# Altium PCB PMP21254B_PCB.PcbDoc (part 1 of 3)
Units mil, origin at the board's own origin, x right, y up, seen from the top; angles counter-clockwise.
Board outline 5000 x 7000 mil, 8 copper layers (Top Layer, Signal Layer 1, Signal Layer 2, Signal Layer 3, Signal Layer 4, Signal Layer 5, Signal Layer 6, Bottom Layer), stack 63 mil thick; 205 components, 78 nets, 623 pads, 1087 vias.
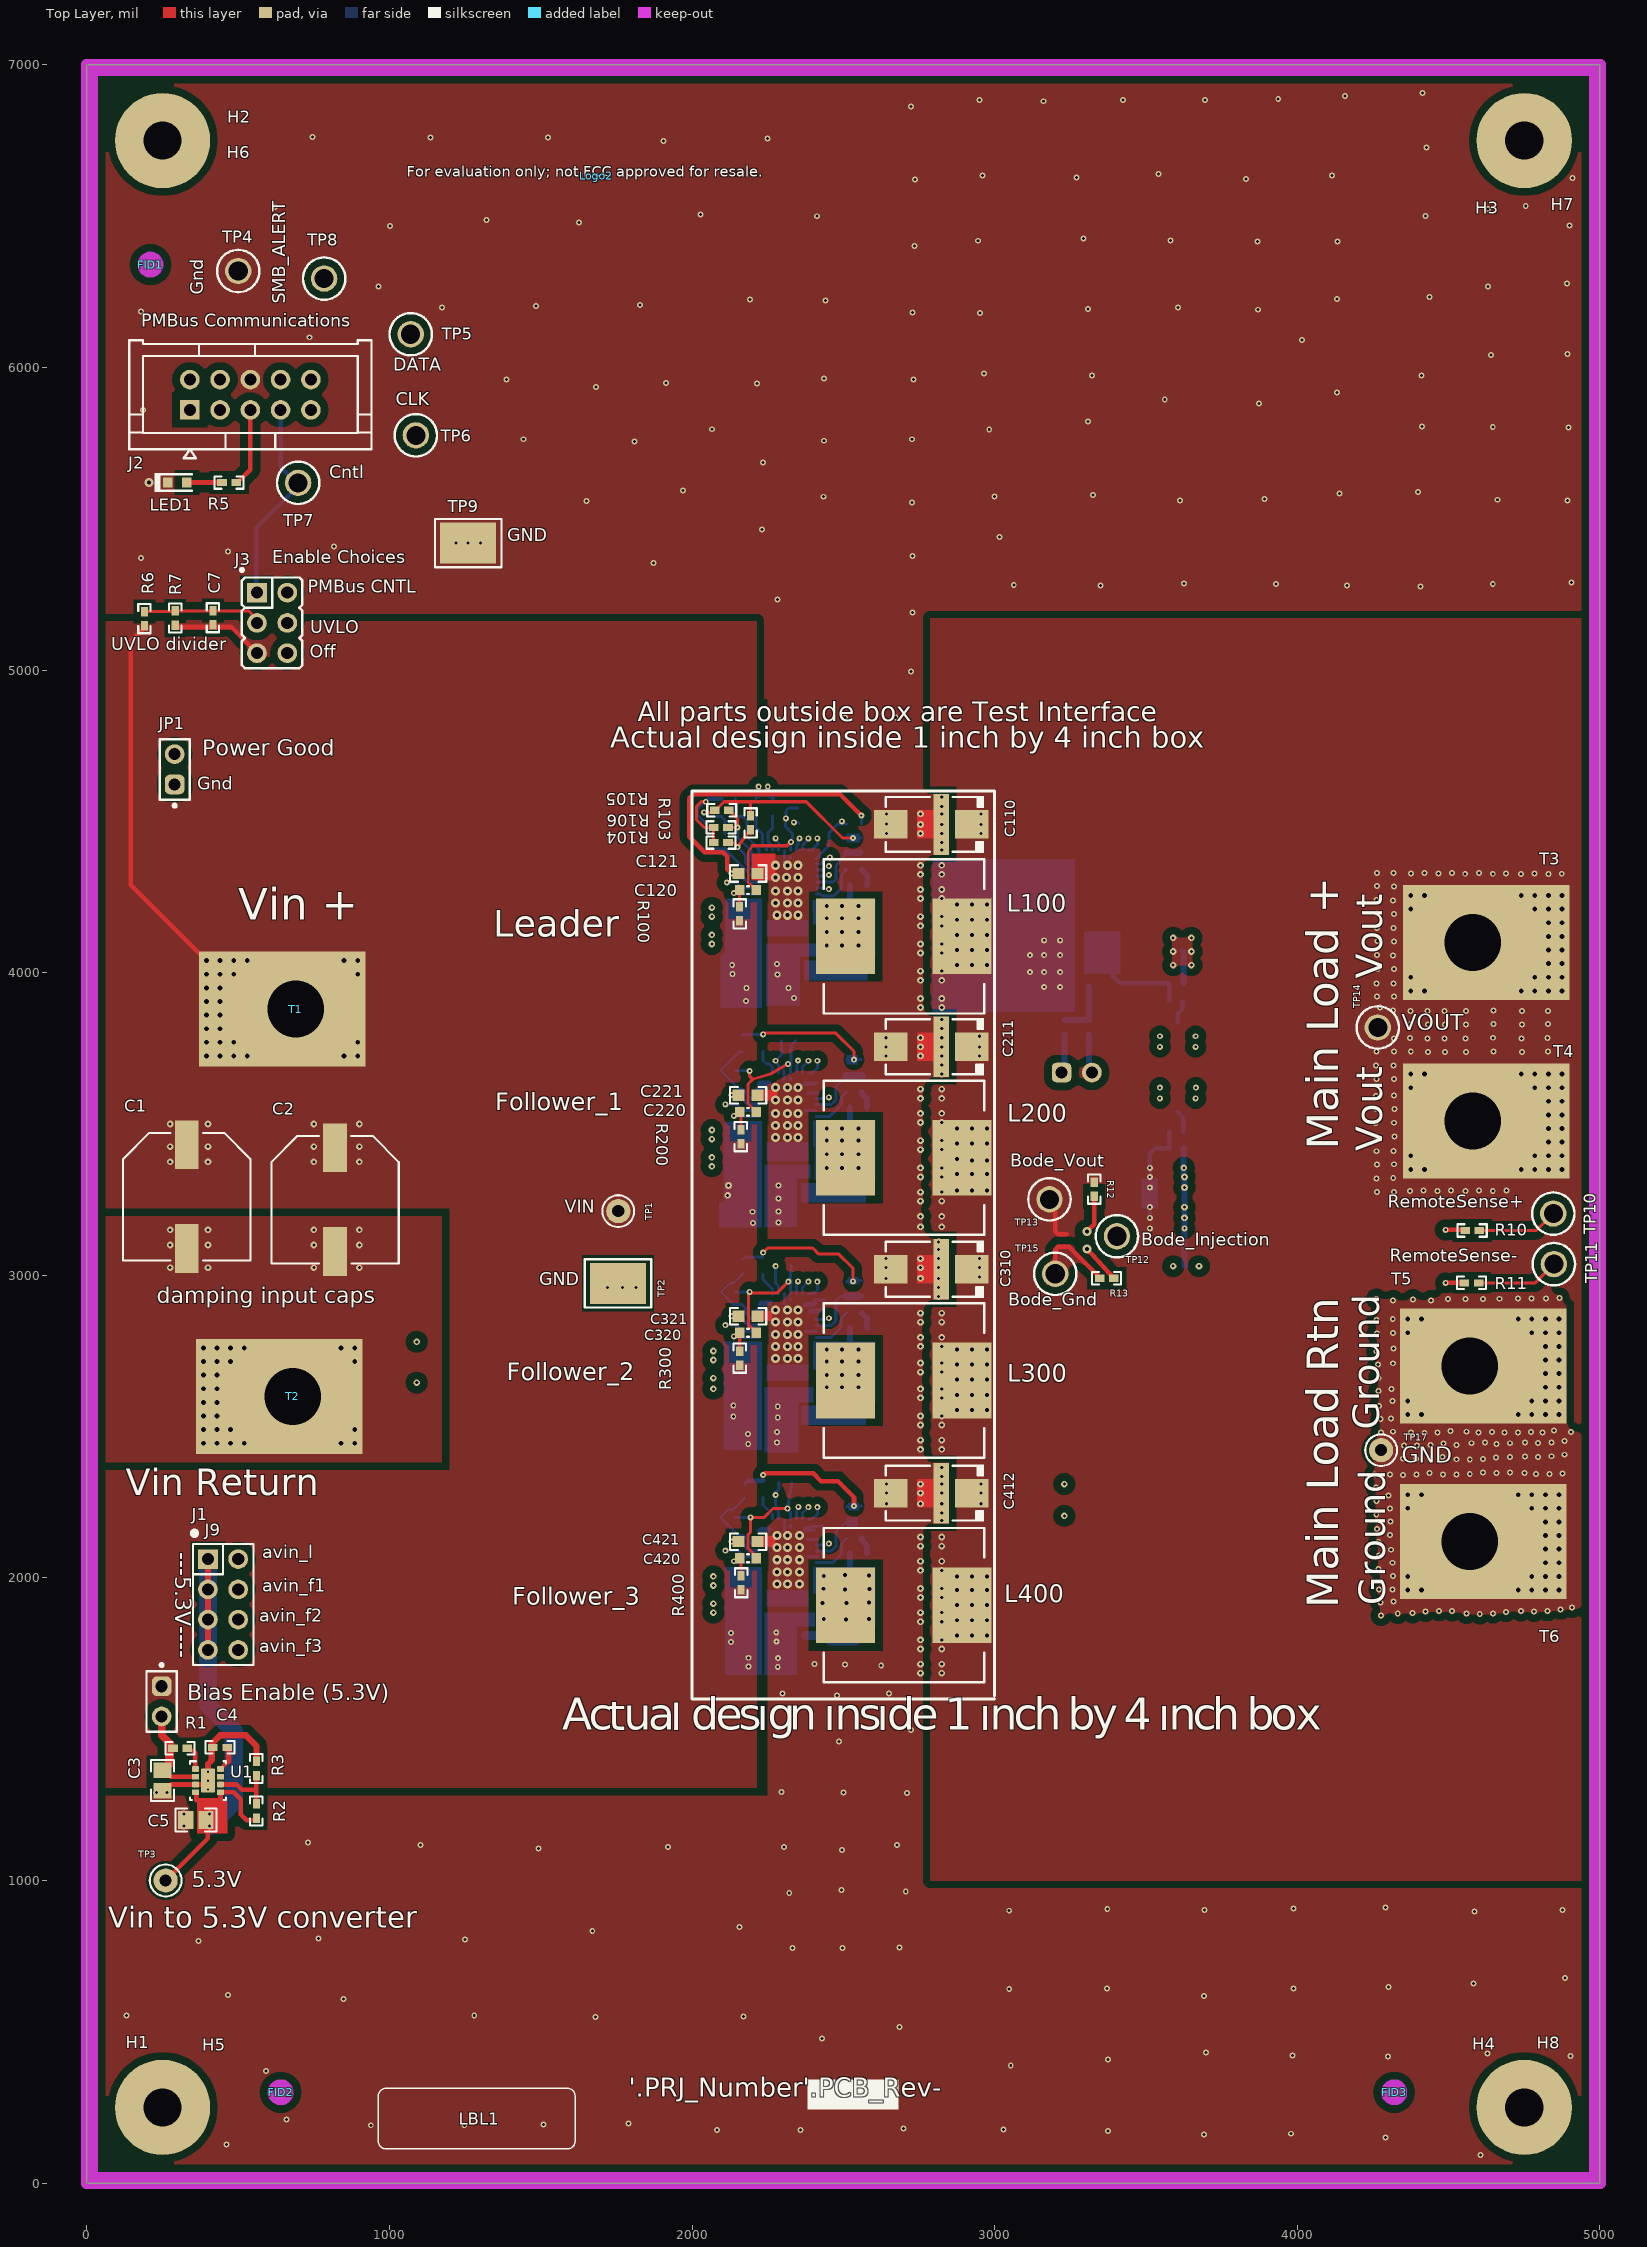
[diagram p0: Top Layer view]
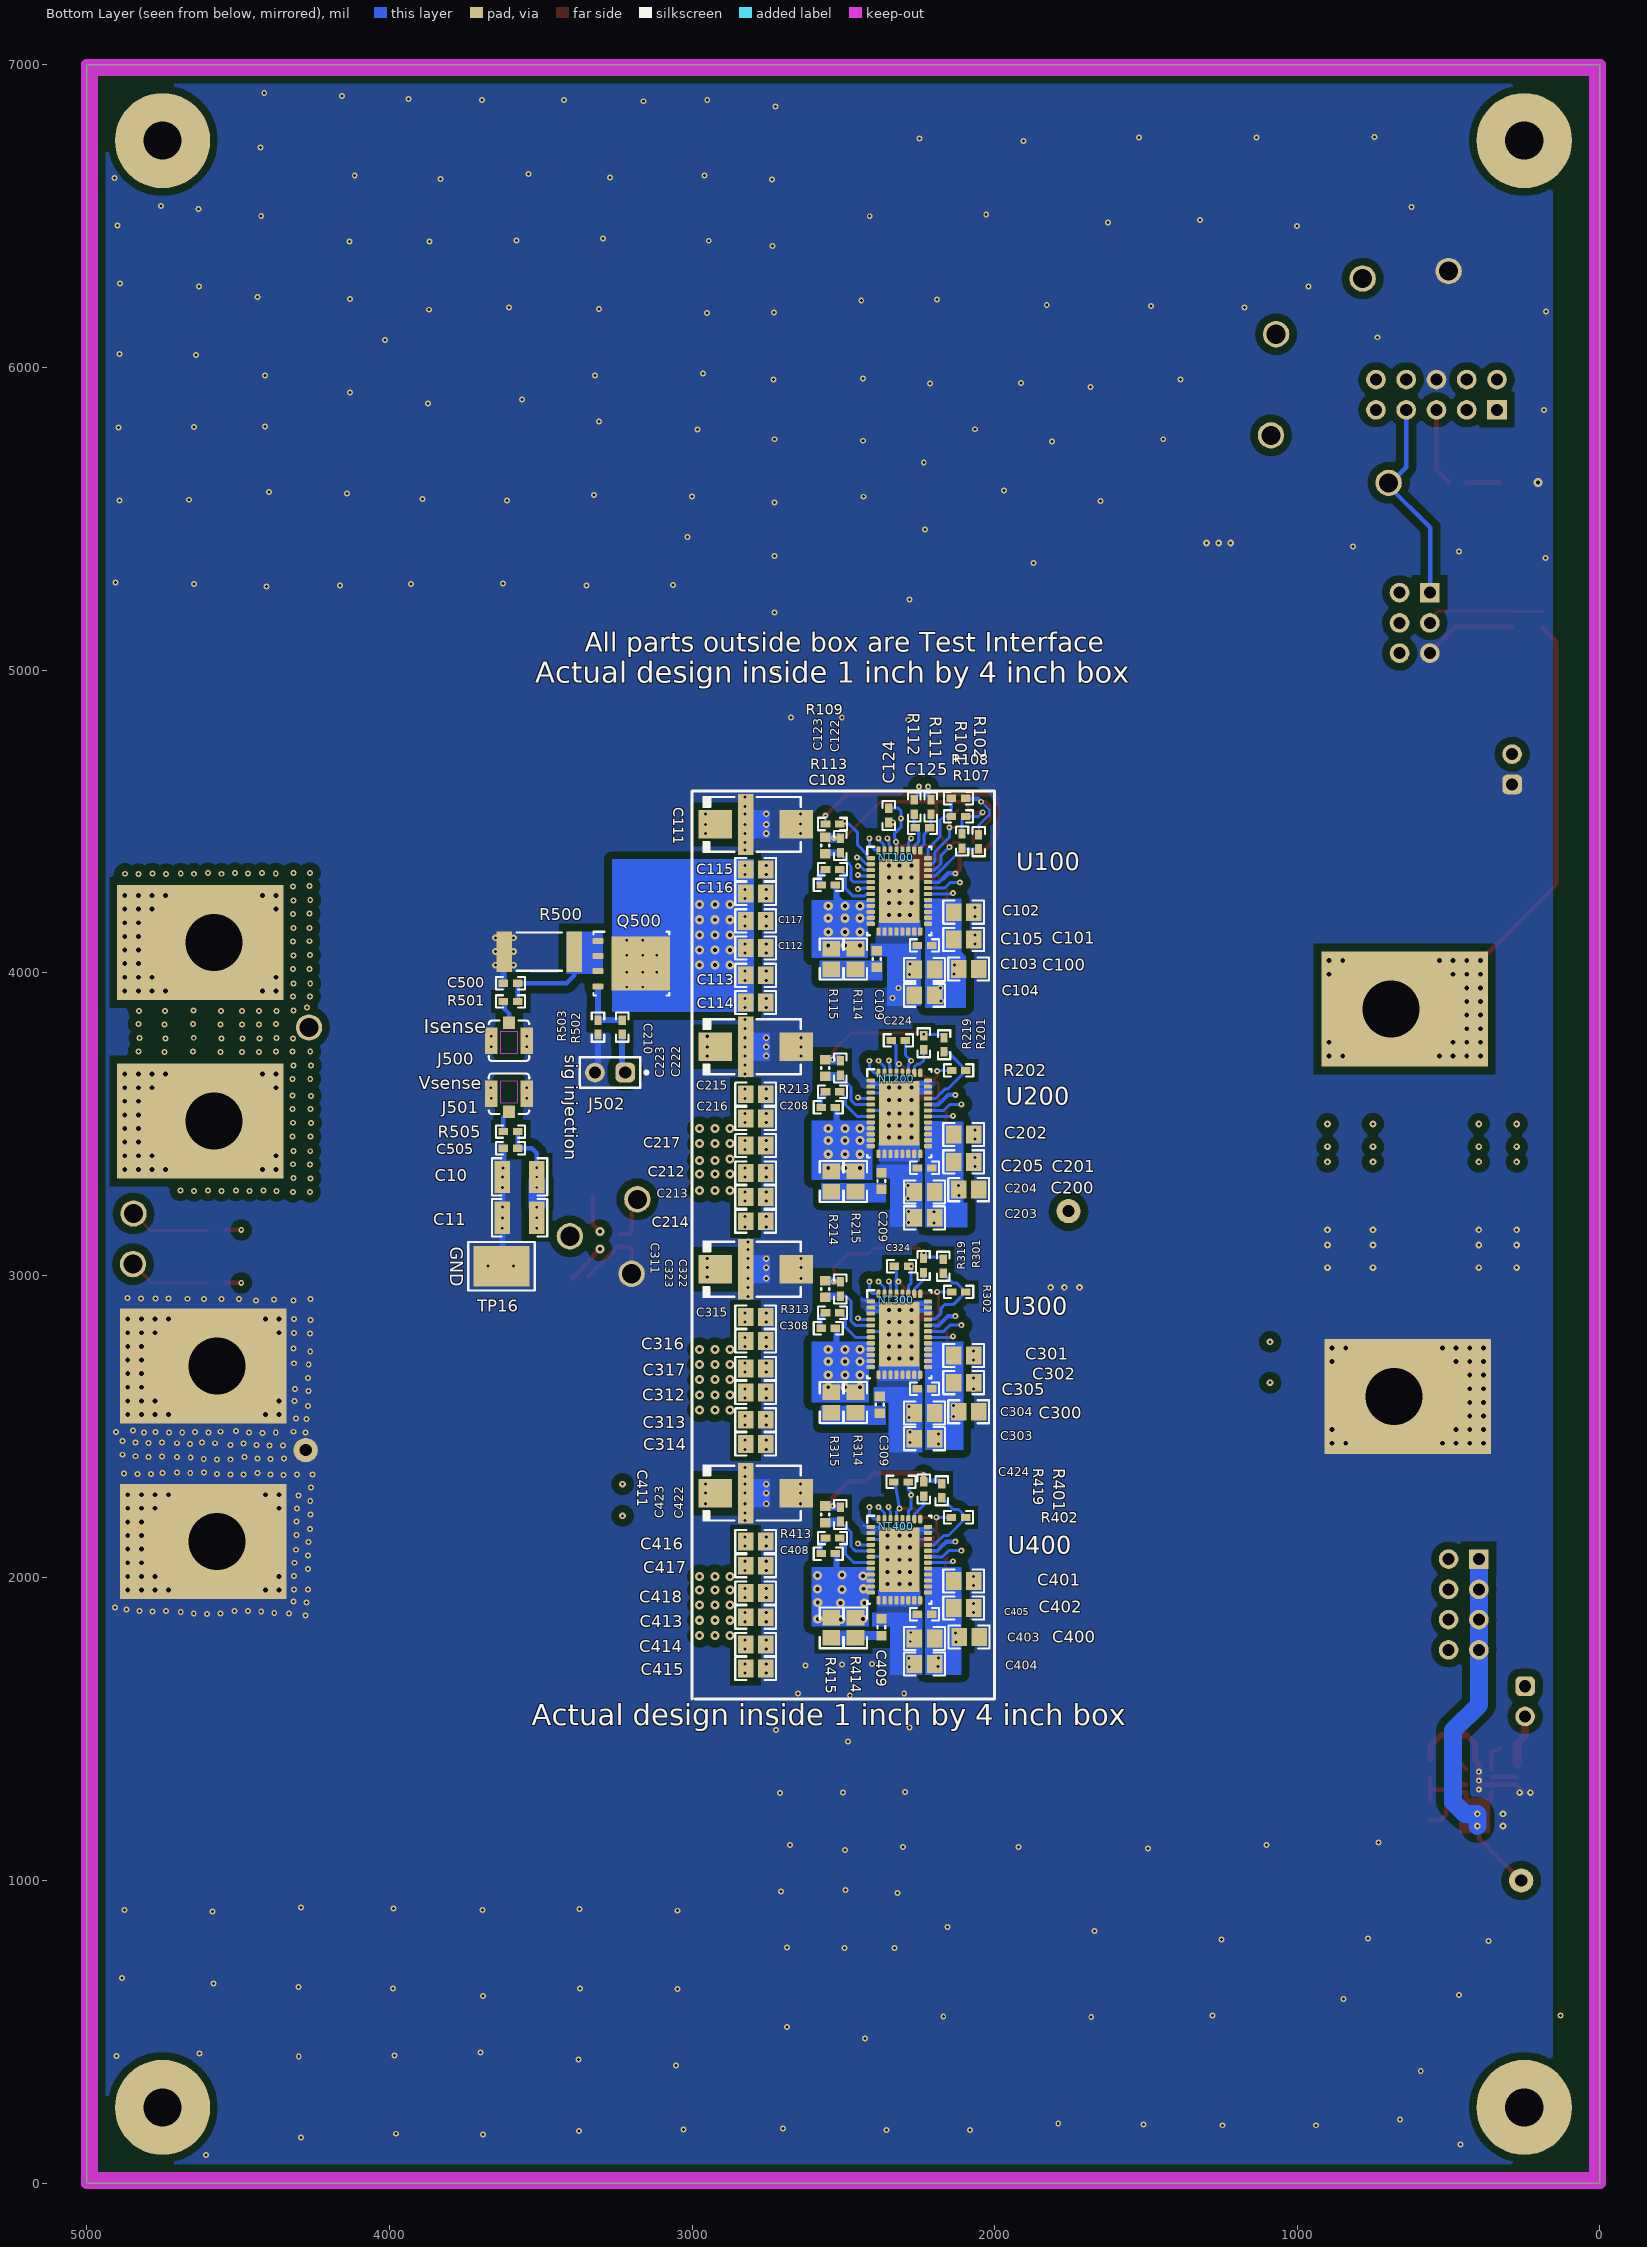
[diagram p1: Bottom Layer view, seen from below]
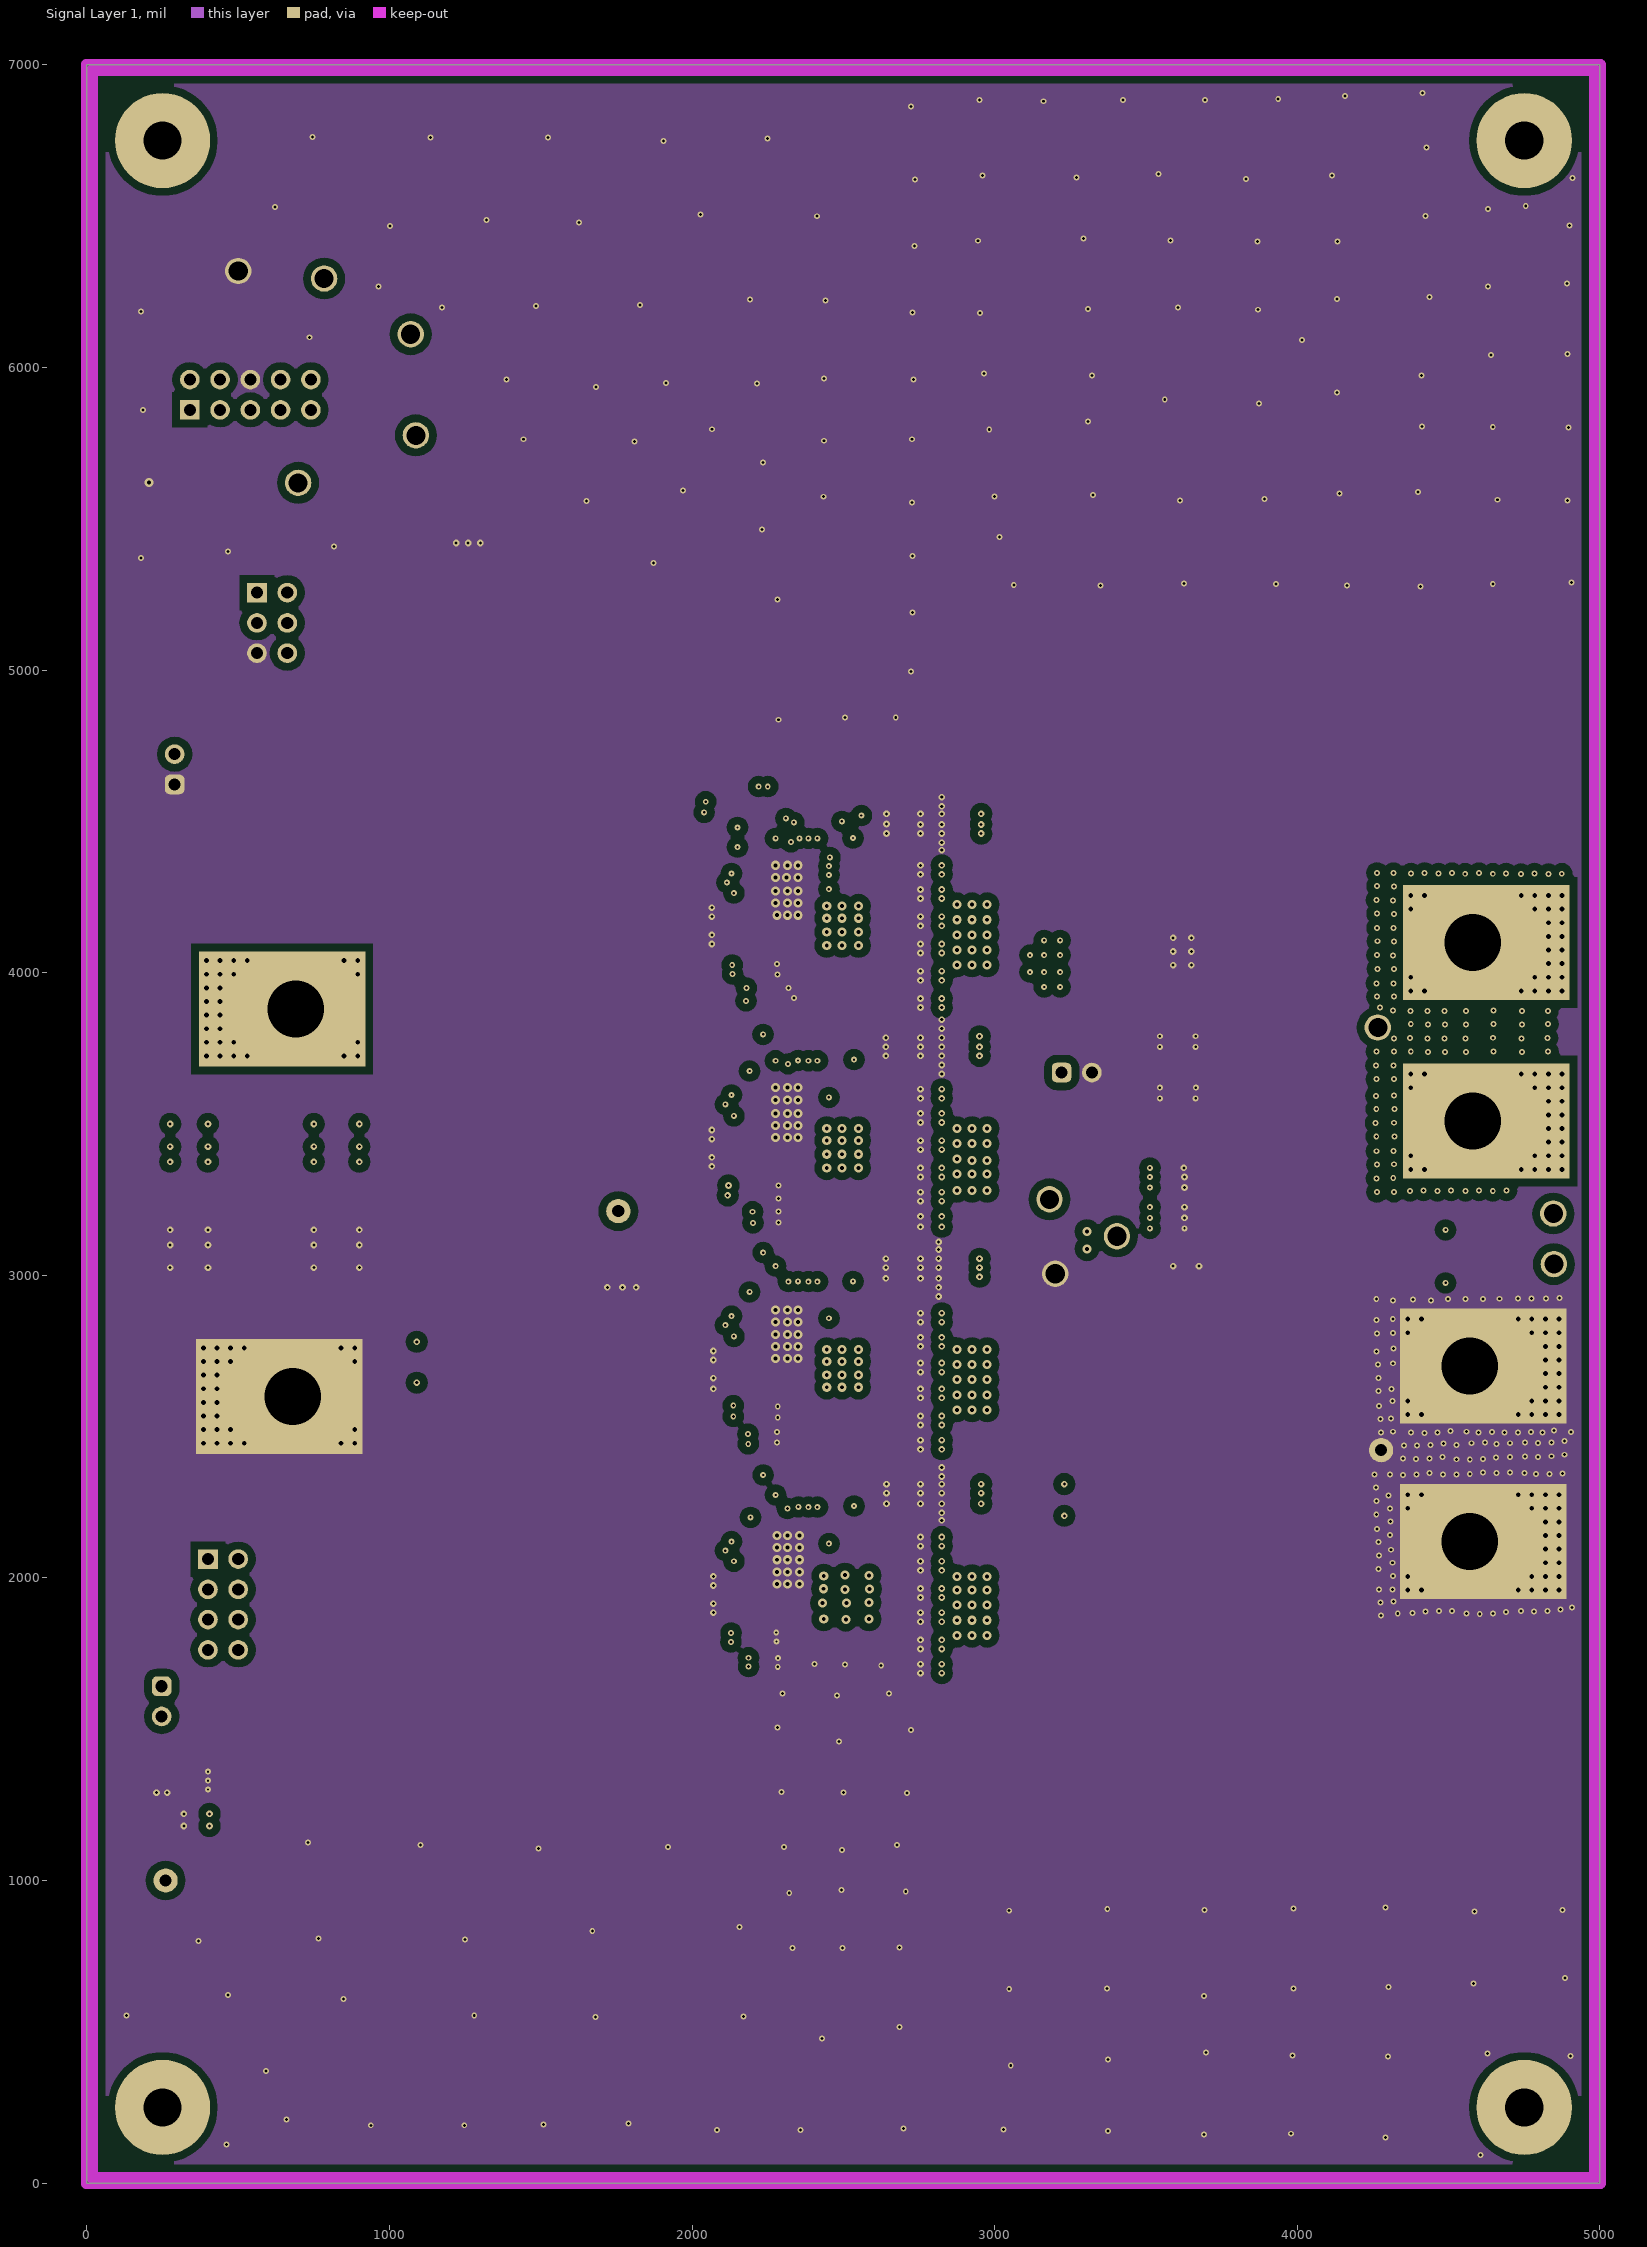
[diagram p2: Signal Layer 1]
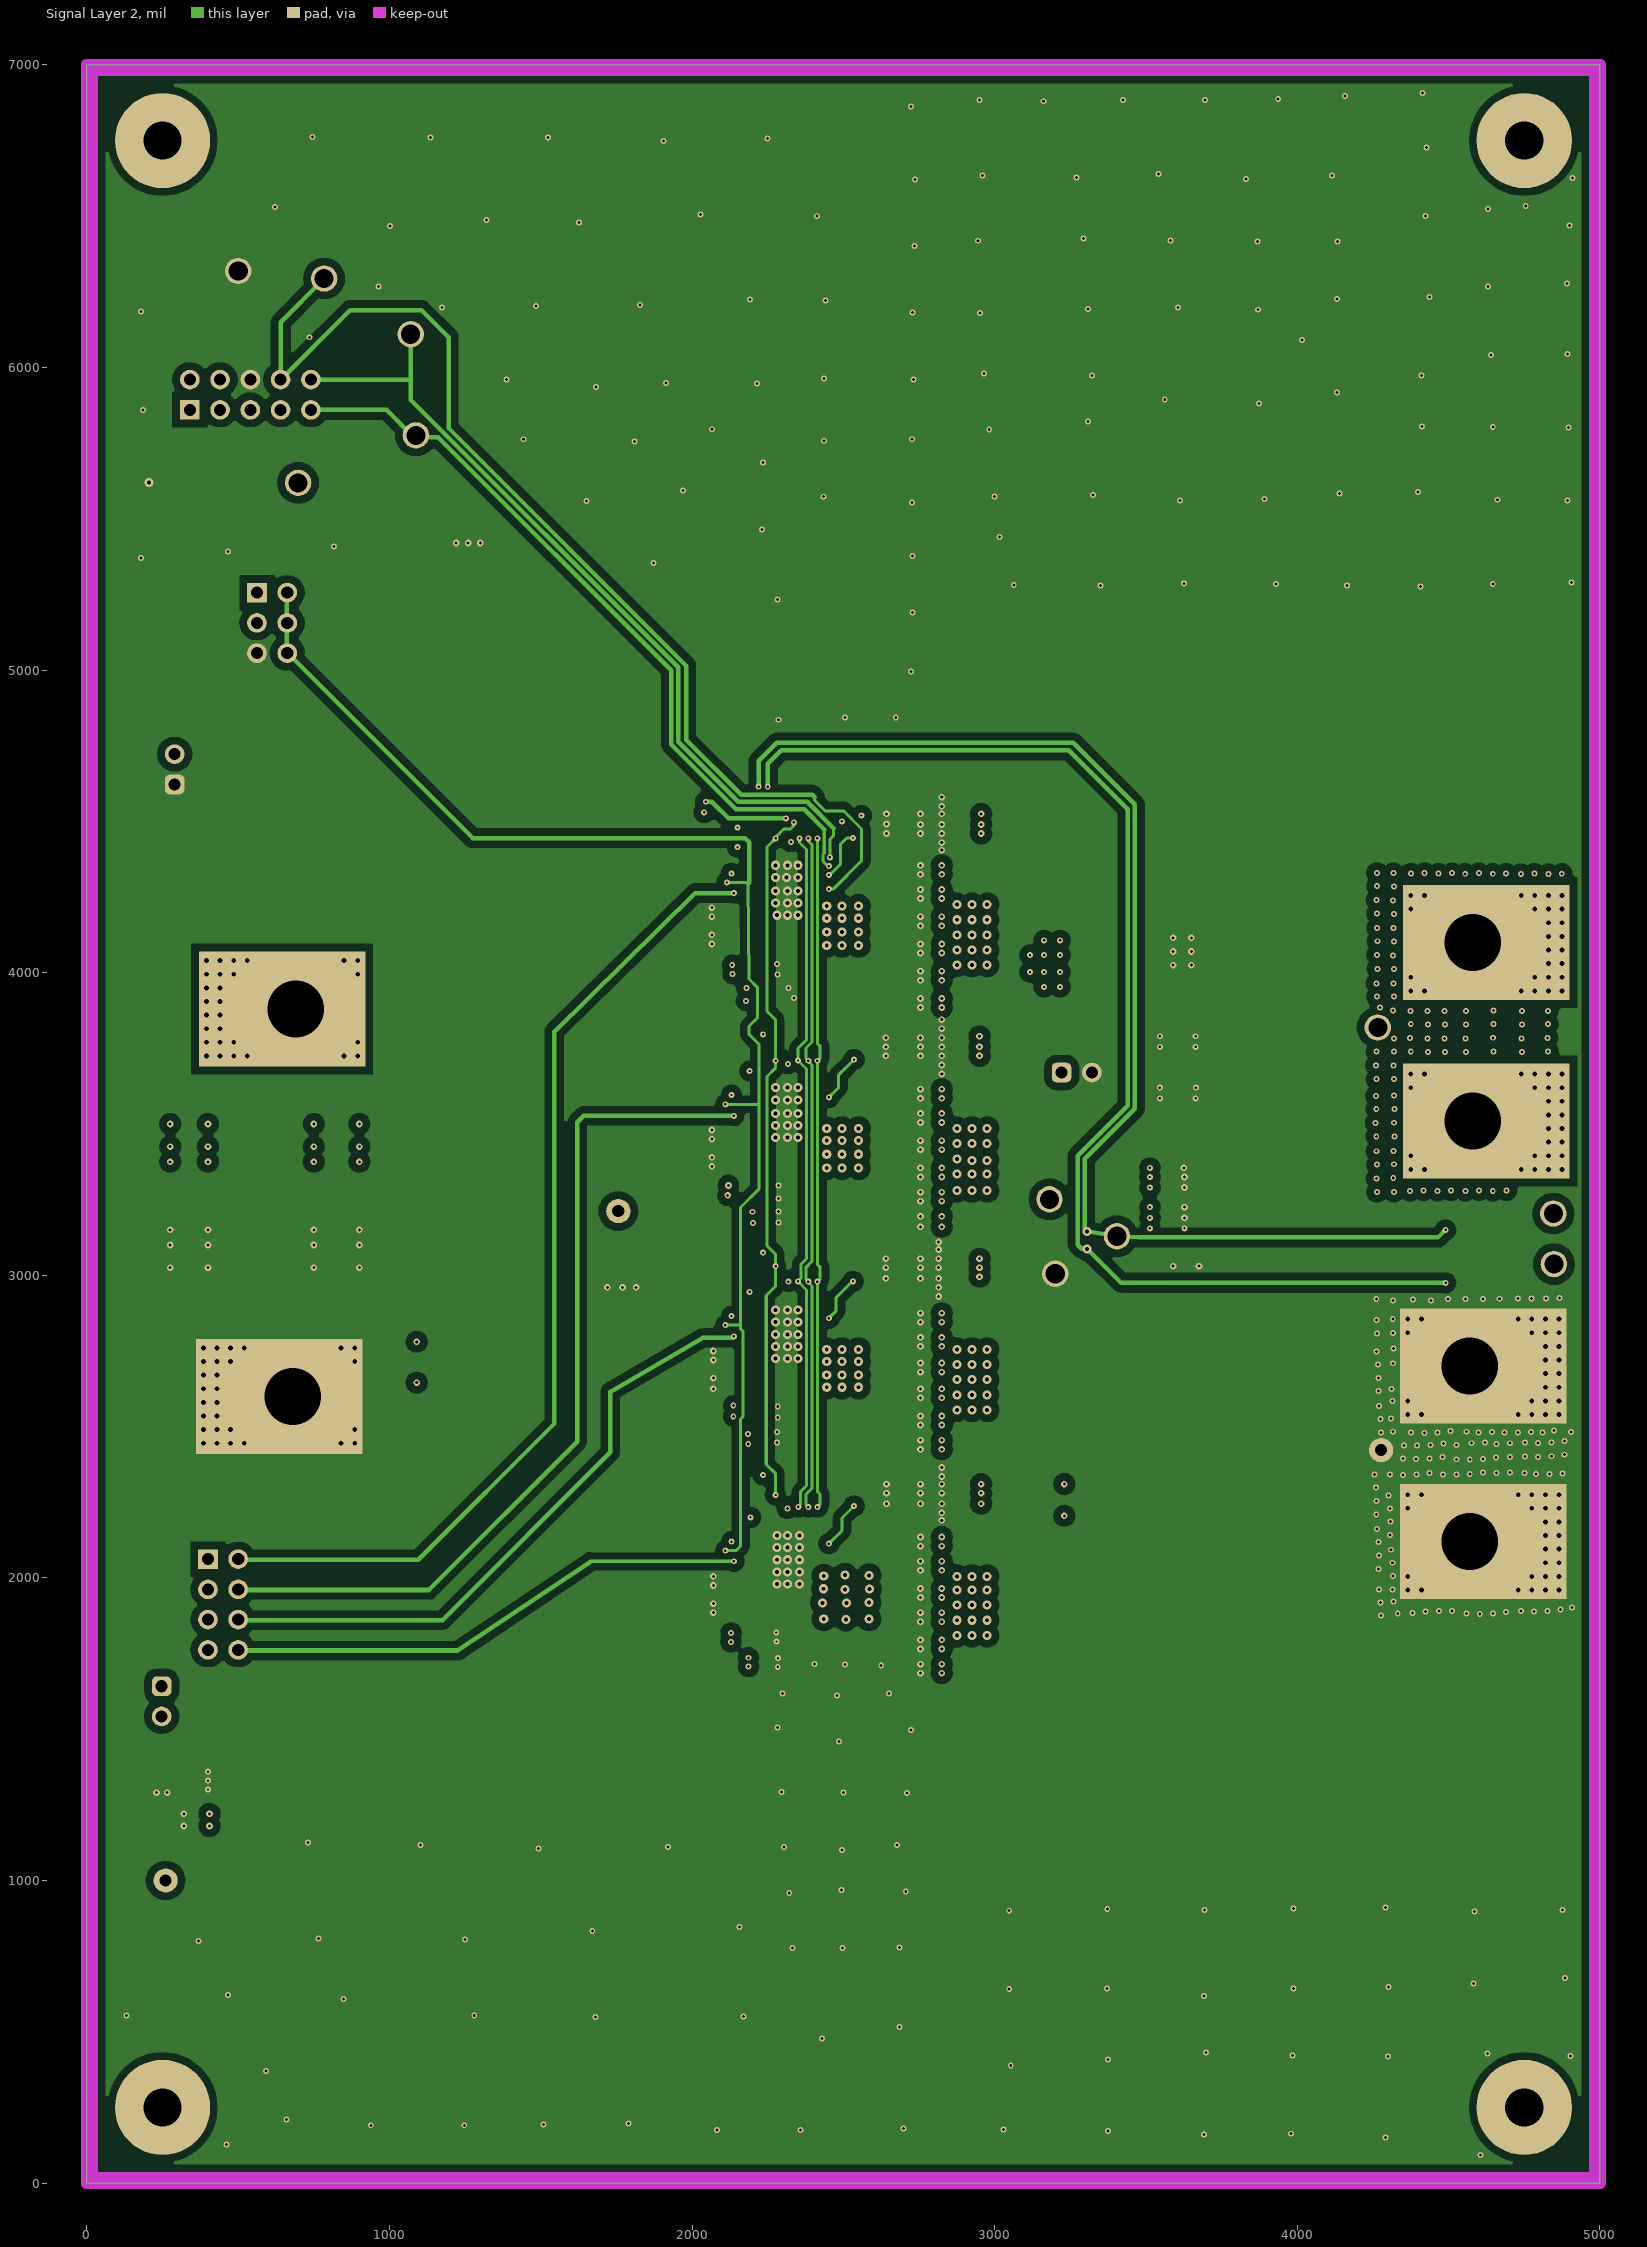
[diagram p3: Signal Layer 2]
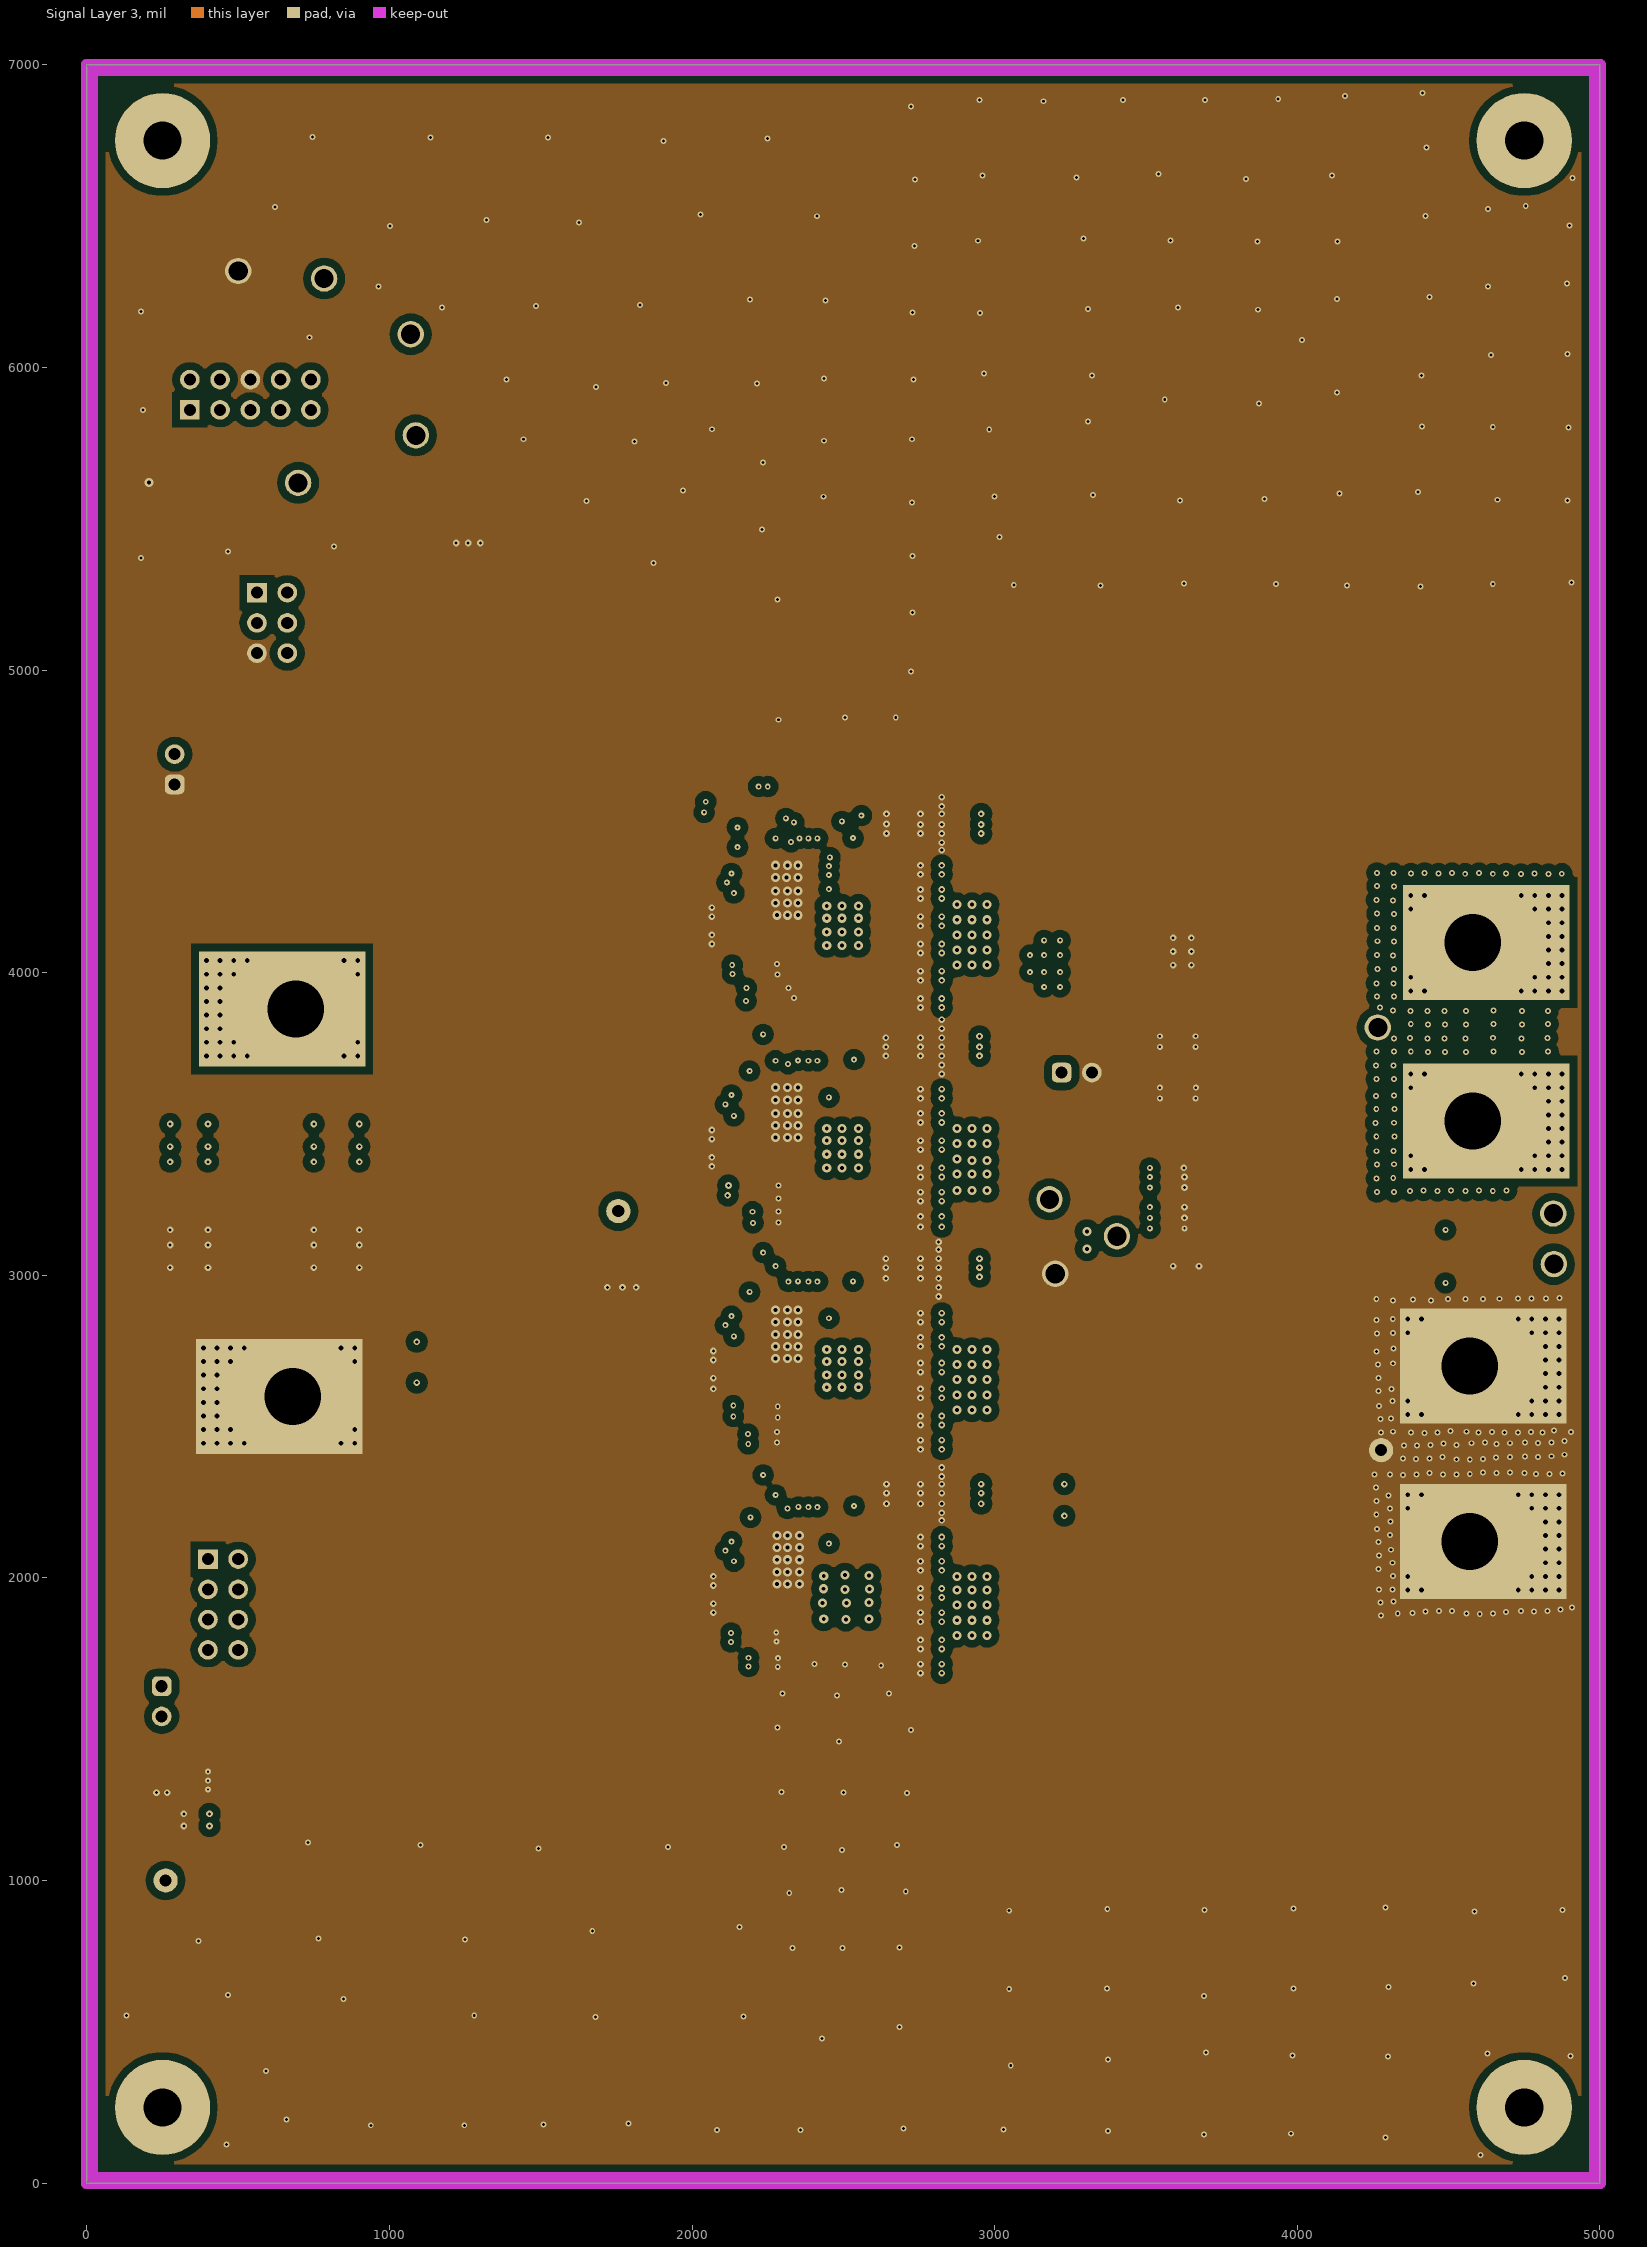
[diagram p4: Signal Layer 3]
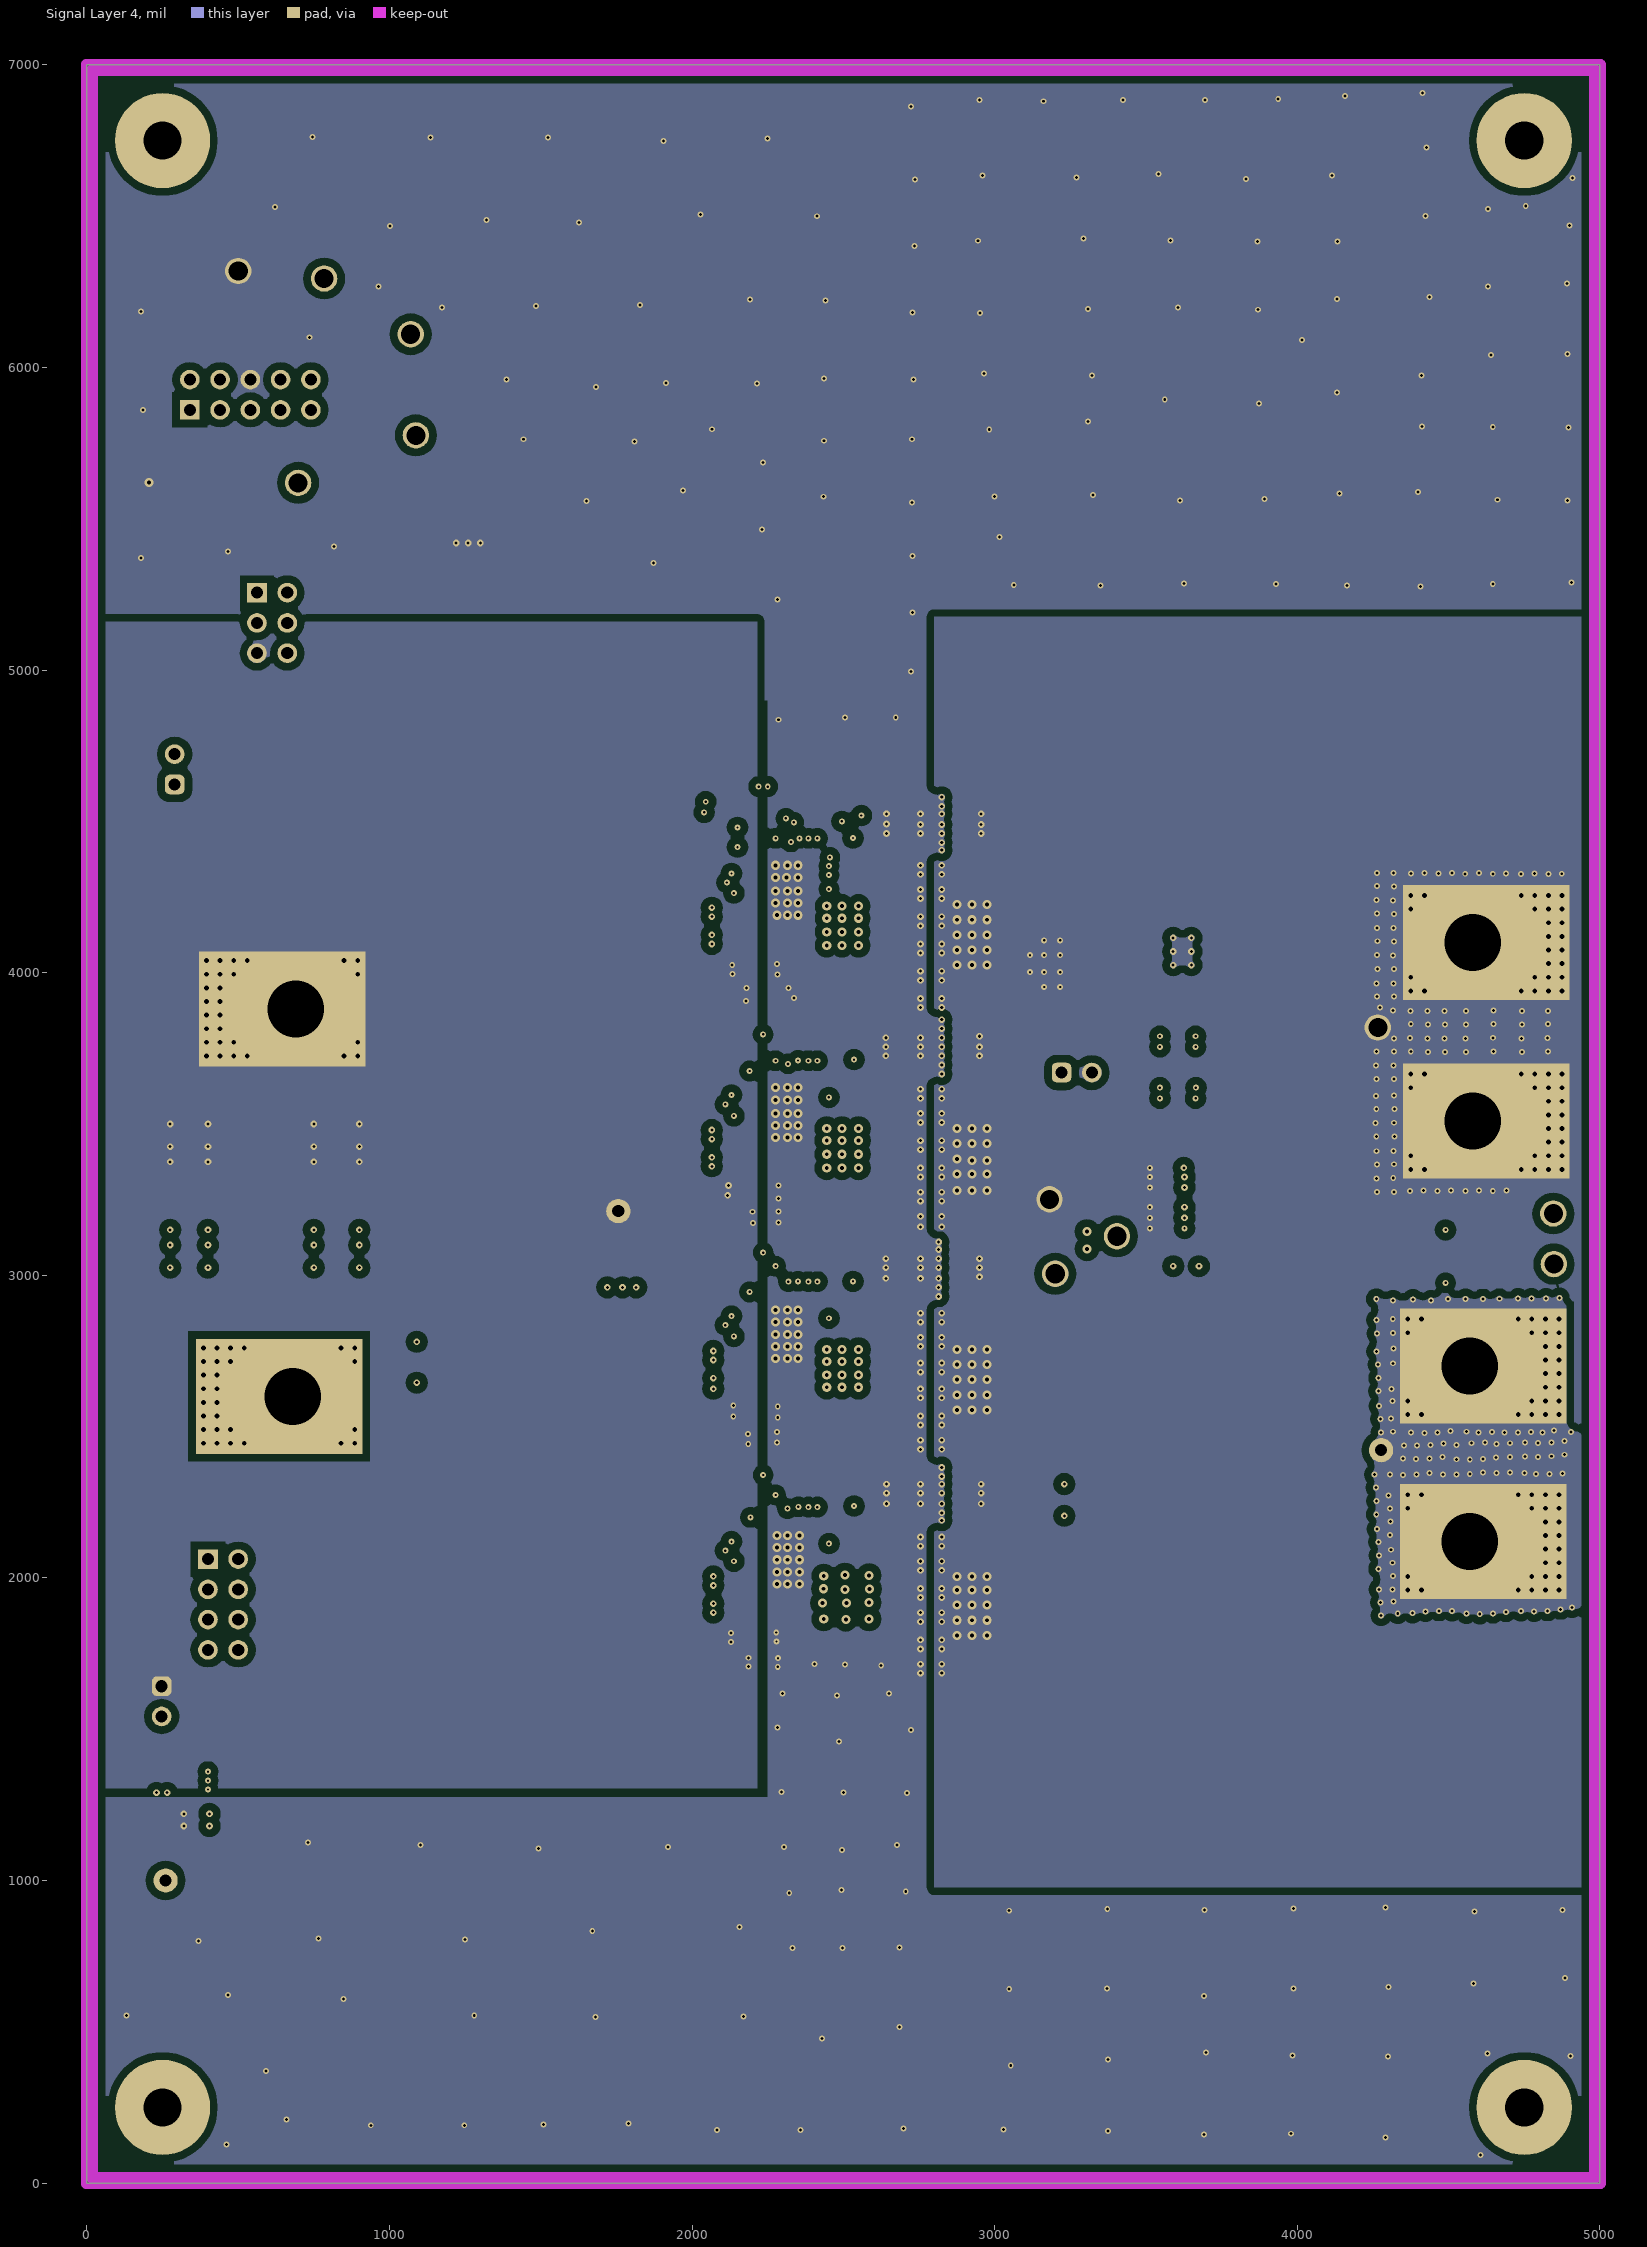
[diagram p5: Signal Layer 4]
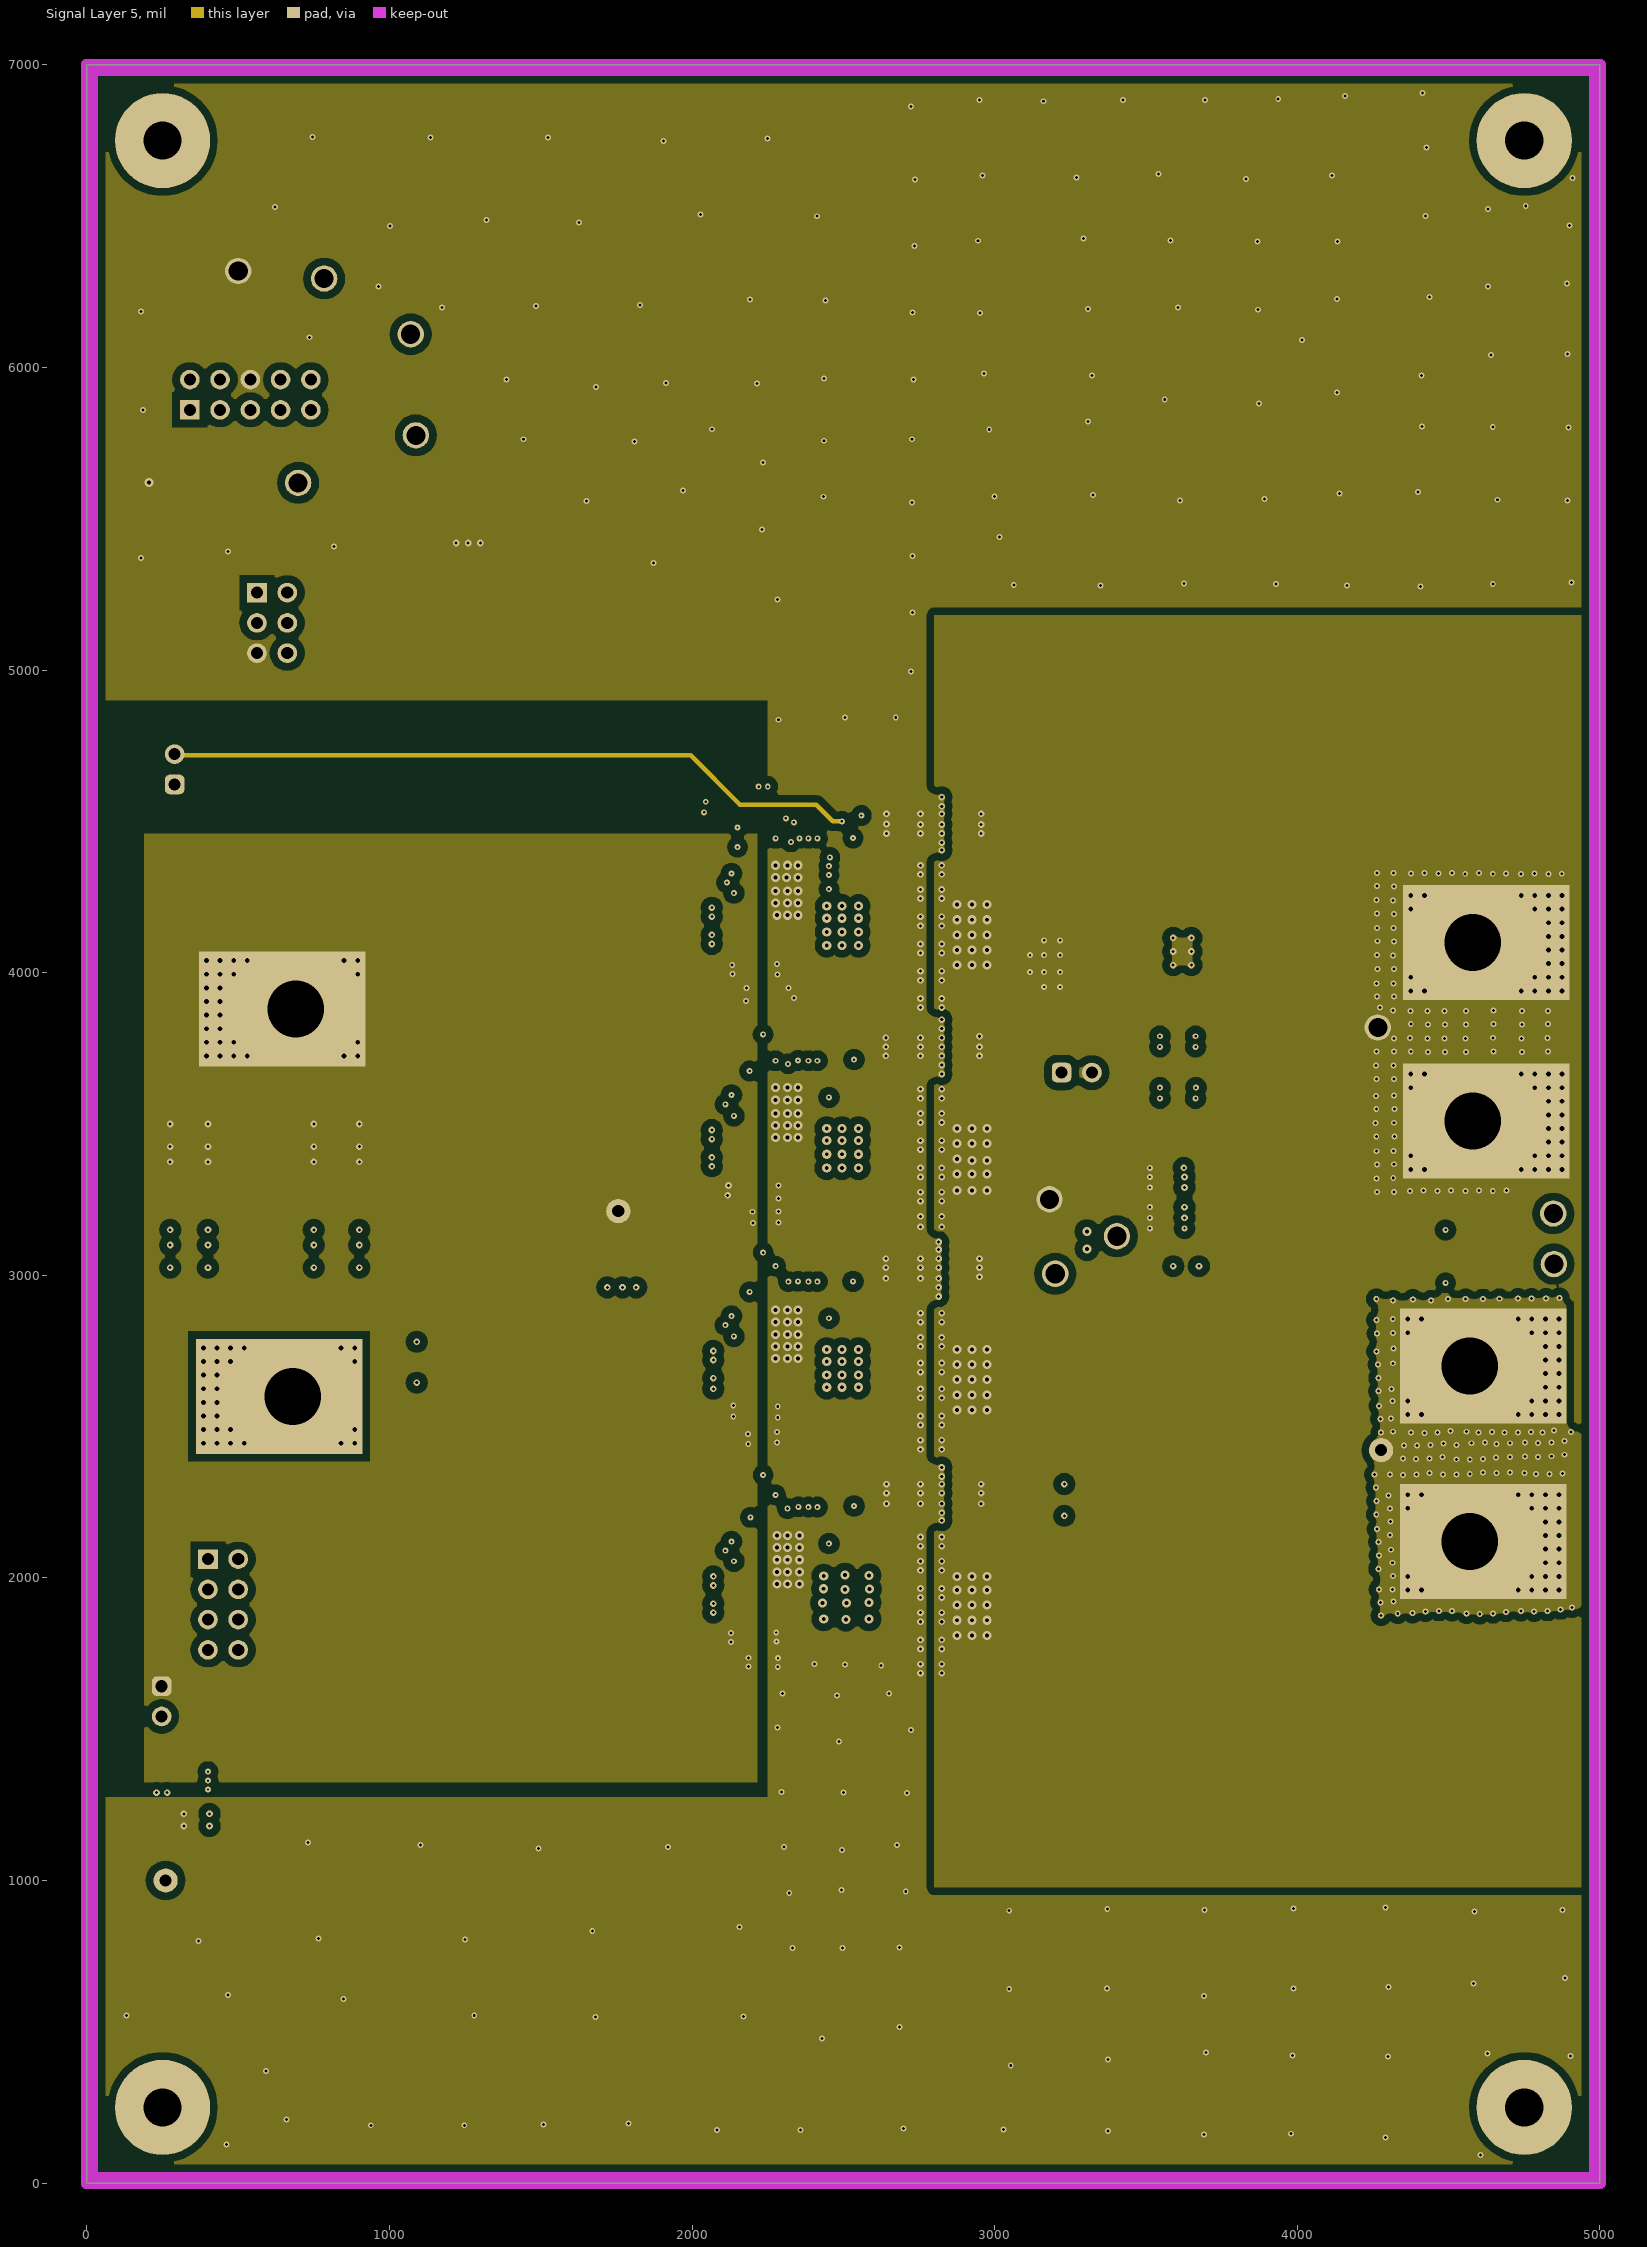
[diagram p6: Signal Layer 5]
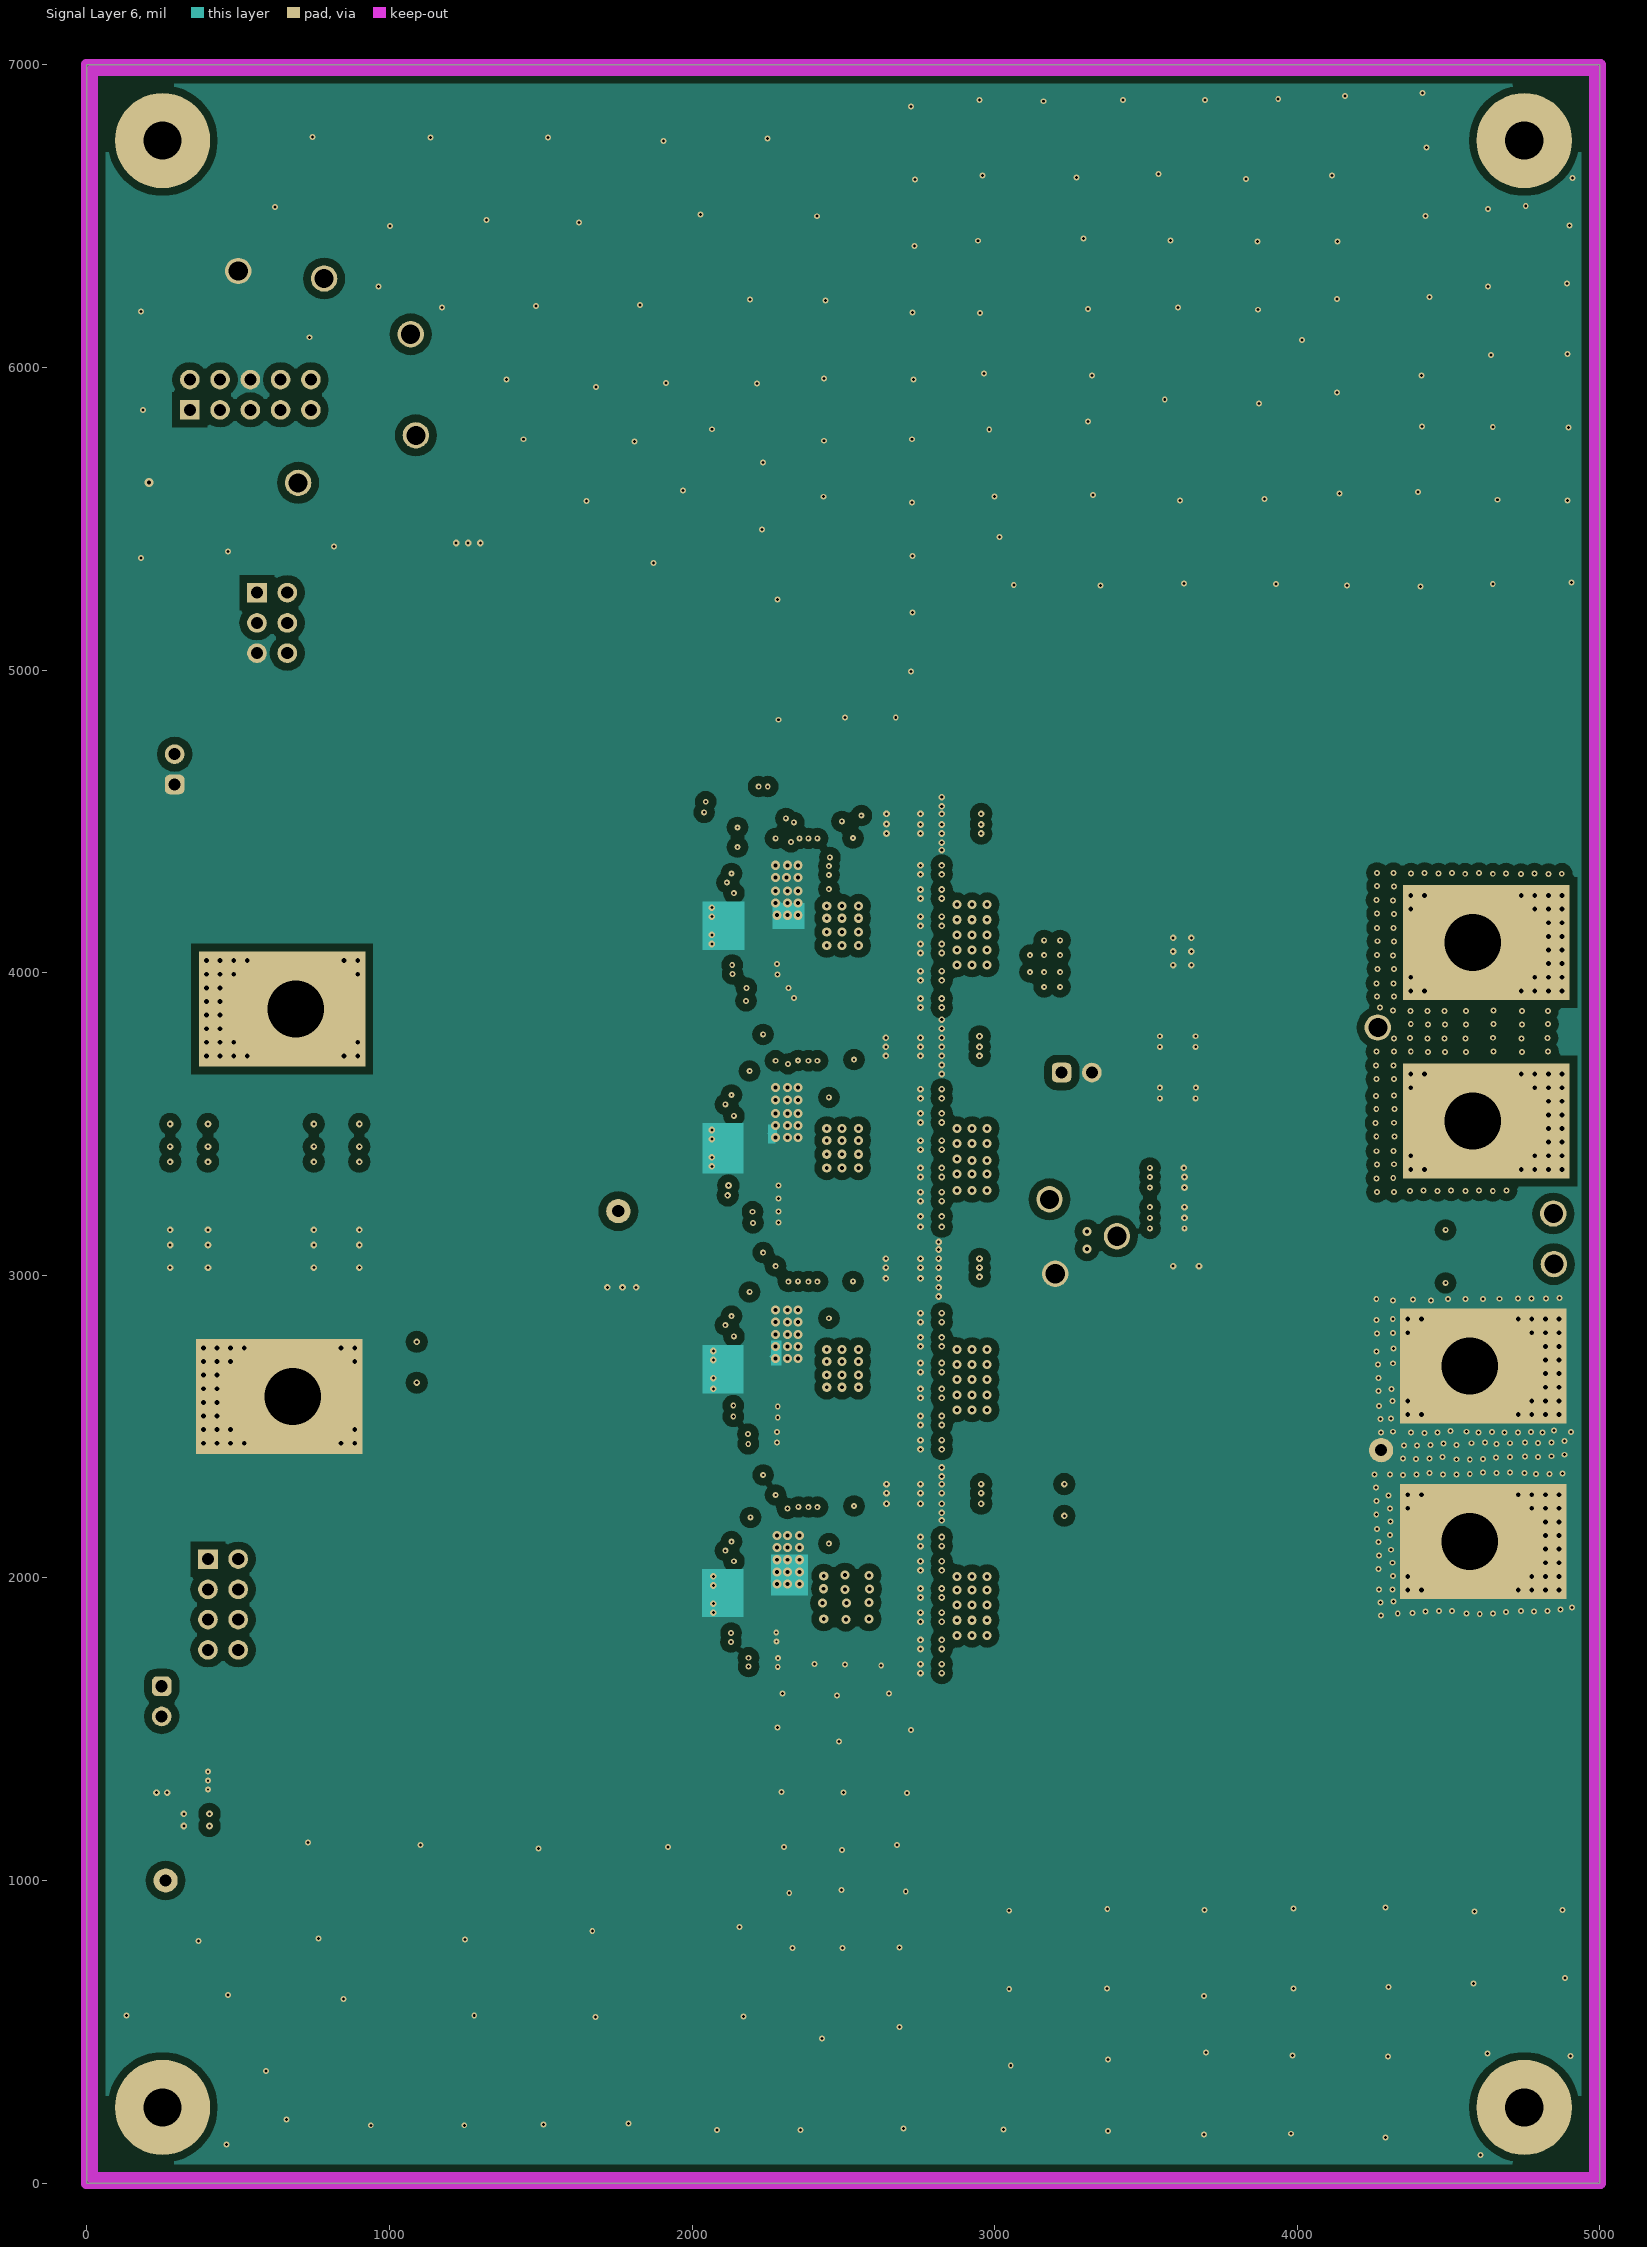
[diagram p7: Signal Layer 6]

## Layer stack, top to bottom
Top Solder: solder mask 0.4, Solder Resist, Dk 3.5
Top Layer: signal copper 2.1
Dielectric1: core 6, FR-4, Dk 4.8
Signal Layer 1: signal copper 2.8
Dielectric 2: dielectric 6, Dk 4.2
Signal Layer 2: signal copper 2.8
Dielectric 3: dielectric 6, Dk 4.2
Signal Layer 3: signal copper 2.8
Dielectric 4: dielectric 6, Dk 4.2
Signal Layer 4: signal copper 2.8
Dielectric 5: dielectric 6, Dk 4.2
Signal Layer 5: signal copper 2.8
Dielectric 6: dielectric 6, Dk 4.2
Signal Layer 6: signal copper 2.8
Dielectric 7: dielectric 6, Dk 4.2
Bottom Layer: signal copper 2.1
Bottom Solder: solder mask 0.4, Solder Resist, Dk 3.5

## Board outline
0,0 5000,0 5000,7000 0,7000

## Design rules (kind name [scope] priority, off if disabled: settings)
AcuteAngle [All] p1: minimum=4.50000000000000E+0001 checktracksonly=FALSE
AssemblyTestPointUsage [All] p1: valid=2
BoardOutlineClearance BoardOutlineClearance_MountingHoles [OnCopper and InComponentClass('Mounting Holes')] p1: gap=40 ignorepadtopadclearanceinfootprint=FALSE
BoardOutlineClearance BoardOutlineClearance_Poly [OnCopper and IsPoly] p2: gap=25 ignorepadtopadclearanceinfootprint=FALSE
BoardOutlineClearance [OnCopper and Not InComponentClass('Logo') and not InComponentClass('FiducialMark') and not InRegion(1000,500,4000,800) and not InPoly] p3: gap=75 ignorepadtopadclearanceinfootprint=FALSE
Clearance Clearance_Keepouts [((IsTrack Or IsArc) And Not InPoly) And IsFree and IsKeepOut vs ((IsTrack Or IsArc) And Not InPoly) And IsFree and IsKeepOut] p1: gap=0 ignorepadtopadclearanceinfootprint=FALSE
Clearance Clearance_Poly [InPolygon] p2: gap=25 ignorepadtopadclearanceinfootprint=FALSE except(0: Arc-Hole Track-Hole SMDPad-Hole THPad-Hole Via-Hole Fill-Hole Poly-Hole Region-Hole Text-Hole)
Clearance Clearance_FiducialMark [IsKeepOut and InComponentClass('FiducialMark') vs IsPad and InComponentClass('FiducialMark')] p3: gap=0 ignorepadtopadclearanceinfootprint=FALSE
Clearance [All] p4: gap=7.87 ignorepadtopadclearanceinfootprint=FALSE except(0: Arc-Hole Track-Hole SMDPad-Hole THPad-Hole Via-Hole Fill-Hole Poly-Hole Region-Hole Text-Hole; 5: Arc-Arc Arc-Track Arc-SMDPad Track-Track Track-SMDPad SMDPad-SMDPad)
ComponentClearance ComponentClearance_MountingHoles_FiducialMarks [InComponentClass('Mounting Holes') vs InComponentClass('FiducialMark')] p1: gap=50 collisioncheckmode=3 verticalgap=10 showdistances=FALSE
ComponentClearance ComponentClearance_Shunt [InComponentClass('Header') vs InComponentClass('Shunt')] p2: gap=0 collisioncheckmode=3 verticalgap=0 showdistances=FALSE
ComponentClearance ComponentClearance_Logo [InComponentClass('Logo')] p3: gap=50 collisioncheckmode=3 verticalgap=10 showdistances=FALSE
ComponentClearance ComponentClearance_ScrewToNut [(HasFootprint('NY PMS 440 0025 PH')) vs (HasFootprint('Keystone_1902C'))] p4: gap=5 collisioncheckmode=3 verticalgap=10 showdistances=FALSE
ComponentClearance ComponentClearance_MountingHoles [InComponentClass('Mounting Holes')] p5: gap=250 collisioncheckmode=3 verticalgap=100000 showdistances=FALSE
ComponentClearance ComponentClearance_SmallPassives [HasFootprint('0201*') or HasFootprint('0402*') or HasFootprint('0508') or HasFootprint('0603*') or HasFootprint('0612') or HasFootprint('0805*') or HasFootprint('0815*') or HasFootprint('0830*') or HasFootprint('1206*') or HasFootprint('1210*') or HasFootprint('1808*') or HasFootprint('1812*') or HasFootprint('1825*') or HasFootprint('2010*') or HasFootprint('2220*') or HasFootprint('2225*') or HasFootprint('2512*') or HasFootprint('2728*') or HasFootprint('3518*') vs HasFootprint('0201*') or HasFootprint('0402*') or HasFootprint('0508') or HasFootprint('0603*') or HasFootprint('0612') or HasFootprint('0805*') or HasFootprint('0815*') or HasFootprint('0830*') or HasFootprint('1206*') or HasFootprint('1210*') or HasFootprint('1808*') or HasFootprint('1812*') or HasFootprint('1825*') or HasFootprint('2010*') or HasFootprint('2220*') or HasFootprint('2225*') or HasFootprint('2512*') or HasFootprint('2728*') or HasFootprint('3518*')] p6: gap=14.96 collisioncheckmode=3 verticalgap=10 showdistances=FALSE
ComponentClearance ComponentClearance_THtoSMT [IsThruComponent vs IsSMTComponent] p7: gap=30 collisioncheckmode=3 verticalgap=30 showdistances=FALSE
ComponentClearance ComponentClearance_THtoTH [IsThruComponent vs IsThruComponent] p8: gap=30 collisioncheckmode=3 verticalgap=30 showdistances=FALSE
ComponentClearance [All] p9: gap=30 collisioncheckmode=3 verticalgap=10 showdistances=FALSE
DiffPairsRouting [All] p1: maxlimit=100 minlimit=10 mostfreqgap=10 toplayer_minwidth=15 toplayer_maxwidth=15 toplayer_prefwidth=15 midlayer1_minwidth=15 midlayer1_maxwidth=15 midlayer1_prefwidth=15 midlayer2_minwidth=15 midlayer2_maxwidth=15 midlayer2_prefwidth=15 midlayer3_minwidth=15 midlayer3_maxwidth=15 midlayer3_prefwidth=15 midlayer4_minwidth=15 midlayer4_maxwidth=15 midlayer4_prefwidth=15 midlayer5_minwidth=15 midlayer5_maxwidth=15 midlayer5_prefwidth=15 midlayer6_minwidth=15 midlayer6_maxwidth=15 midlayer6_prefwidth=15 bottomlayer_minwidth=15 bottomlayer_maxwidth=15 bottomlayer_prefwidth=15 maxuncoupledlength=1000
FabricationTestPointUsage TestPointUsage [All] p1: valid=2 allowmultiple=FALSE
FabricationTestpoint Testpoint [All] p1: side=3 testpointundercomponent=TRUE minsize=40 maxsize=100 preferedsize=60 minholesize=0 maxholesize=40 preferedholesize=32 testpointgrid=1 allowsidetop=TRUE allowsidebottom=TRUE usegrid=TRUE gridtolerance=0.01
FanoutControl Fanout_LCC [IsLCC] p1: bgadir=Out bgaviamode=Centered fanoutstyle=Auto fanoutdirection=Alternating viagrid=1 // Fanout_LCC (Default Rule)
FanoutControl Fanout_BGA [IsBGA] p2: bgadir=Out bgaviamode=Centered fanoutstyle=Auto fanoutdirection=Alternating viagrid=1 // Fanout_BGA (Default Rule)
FanoutControl Fanout_Default [All] p4: bgadir=Out bgaviamode=Centered fanoutstyle=Auto fanoutdirection=Alternating viagrid=1 // Fanout_Default (Default Rule)
FanoutControl Fanout_Small [(CompPinCount < 5)] p5: bgadir=Out bgaviamode=Centered fanoutstyle=Auto fanoutdirection=OutThenIn viagrid=1 // Fanout_Small (Default Rule)
HoleSize [All] p1: absolutevalues=TRUE maxlimit=251 minlimit=7.87 maxpercent=80.000 minpercent=20.000
MinimumAnnularRing MinimumAnnularRing_ThermalPadVias [IsVia and InAnyComponent] p1: minimumring=4.9
MinimumAnnularRing [All] p2: minimumring=4.9
MinimumSolderMaskSliver MinimumSolderMaskSliver_Logo [InComponentClass('Logo') vs InComponentClass('Logo')] p1: minsoldermaskwidth=0.7
MinimumSolderMaskSliver [All] p2: minsoldermaskwidth=3.94
PlaneConnect [All] p1: planeconnectstyle=Direct reliefexpansion=10 reliefentries=4 reliefconductorwidth=10 reliefairgap=10
PolygonConnect [All] p1: connectstyle=Direct reliefconductorwidth=10 reliefentries=4 polygonreliefangle="90 Angle" airgapwidth=10
RoutingVias ThermalPadVias [IsVia and InAnyComponent] p1: holewidth=7.87 width=19.68 viastyle="Through Hole" minholewidth=7.87 minwidth=19.68 maxholewidth=17 maxwidth=33
RoutingVias [All] p2: holewidth=16 width=34 viastyle="Through Hole" minholewidth=7.87 minwidth=19.68 maxholewidth=40 maxwidth=65
SilkToBoardRegionClearance [Not ((IsComment or IsDesignator) And (Hide <> 'False')) and not InRegion(1000,500,4000,800)] p1:
SilkToSilkClearance SilkToSilkClearance_Pb-FreeLogo [(HasFootprint('Pb-Free_Overlay_Medium') OR HasFootprint('Pb-Free_Overlay_Small')) vs (HasFootprint('Pb-Free_Overlay_Medium') OR HasFootprint('Pb-Free_Overlay_Small'))] p1: silktosilkclearance=0
SilkToSilkClearance [All] p2: silktosilkclearance=4
SilkToSolderMaskClearance SilkToComponentPadClearance [(IsPad or IsFill or IsRegion) and InAnycomponent] p1: minsilkscreentomaskgap=5 clearancetoexposedcopper=TRUE
SilkToSolderMaskClearance "Silk to Solder Mask Opening" [All] p2: minsilkscreentomaskgap=4 clearancetoexposedcopper=FALSE
SolderMaskExpansion [All] p1: expansion=1.97
Width [All] p1: maxlimit=200 minlimit=6 preferedwidth=10 checkconnectedcopper=TRUE
15 further rules are at their usual default settings.

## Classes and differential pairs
component class "Mounting Holes": H1 H2 H3 H4
component class PMP21254B_Leader&Aux: C1 C2 C3 C4 C5 C7 C10 C11 C100 C101 C102 C103 C104 C105 C108 C109 C110 C111 C112 C113 C114 C115 C116 C117 C120 C121 C122 C123 C124 C125 C500 C505 J1 J2 J3 J9 J500 J501 J502 JP1 L100 LED1 NT100 Q500 R1 R2 R3 R5 R6 R7 R10 R11 R12 R13 R100 R101 R102 R103 R104 R105 R106 R107 R108 R109 R111 R112 R113 R114 R115 R500 R501 R502 R503 R505 T1 T2 T3 T4 T5 T6 TP1 TP2 TP3 TP4 TP5 TP6 TP7 TP8 TP9 TP10 TP11 TP12 TP13 TP14 TP15 TP16 TP17 U1 U100
component class Header: J1 J3 J9 J502 JP1
component class Label: LBL1
component class FiducialMark: FID1 FID2 FID3
component class PMP21254B_Followers&Hardware: C200 C201 C202 C203 C204 C205 C208 C209 C210 C211 C212 C213 C214 C215 C216 C217 C220 C221 C222 C223 C224 C300 C301 C302 C303 C304 C305 C308 C309 C310 C311 C312 C313 C314 C315 C316 C317 C320 C321 C322 C323 C324 C400 C401 C402 C403 C404 C405 C408 C409 C411 C412 C413 C414 C415 C416 C417 C418 C420 C421 C422 C423 C424 FID1 FID2 FID3 H1 H2 H3 H4 H5 H6 H7 H8 L200 L300 L400 LBL1 Logo2 NT200 NT300 NT400 R200 R201 R202 R213 R214 R215 R219 R300 R301 R302 R313 R314 R315 R319 R400 R401 R402 R413 R414 R415 R419 U200 U300 U400

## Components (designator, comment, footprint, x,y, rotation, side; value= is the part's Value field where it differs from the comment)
C1 "Cap_Polarized" SM_RADIAL_G 330,3260 r270 top value=100uF
C2 "Cap_Polarized" SM_RADIAL_G 820,3250 r270 top value=100uF
C3 "Capacitor" 0805 250,1330 r270 top value=22uF
C4 "C0402C103J5RACTU" 0402 440,1440 r180 top value=0.01uF
C5 "Capacitor" 0805 360,1200 r180 top value=22uF
C7 "Capacitor" 0402_065 416.38,5173 r90 top value=0.1uF
C10 "Capacitor" 1210_270 3570,3325 r180 bottom value=47uF
C11 "Capacitor" 1210_270 3570,3190 r180 bottom value=47uF
C100 "Capacitor" 0805 2086,4012 r0 bottom value=22uF
C101 "Capacitor" 0805 2102.4,4110 r0 bottom value=22uF
C102 "Capacitor" 0805 2102.4,4200 r0 bottom value=22uF
C103 "Capacitor" 0805 2232.4,4010 r180 bottom value=22uF
C104 "Capacitor" 0805 2232.4,3925.55 r180 bottom value=22uF
C105 "Capacitor" 0402 2232.4,4090 r0 bottom value=6800pF
C108 "Capacitor" 0402_065 2550,4290 r180 bottom value=0.1uF
C109 "Capacitor" 0603L 2390,4045.55 r90 bottom value=1000pF
C110 "CAPP_POS1NEG23" GX_3TERM 2790,4490 r180 top value=560uF
C111 "CAPP_POS1NEG23" GX_3TERM 2790,4490 r180 bottom value=560uF
C112 "Capacitor" 0805 2790,4081.46 r180 bottom value=100uF
C113 "Capacitor" 0805 2790,3991.46 r180 bottom value=100uF
C114 "Capacitor" 0805 2790,3901.46 r180 bottom value=100uF
C115 "Capacitor" 0805 2790,4341.46 r180 bottom value=100uF
C116 "Capacitor" 0805 2790,4261.46 r180 bottom value=100uF
C117 "Capacitor" 0805 2790,4171.46 r180 bottom value=100uF
C120 "Capacitor" 0603L 2185,4273 r0 top value=1uF
C121 "Capacitor" 0603 2185,4328 r180 top value=4.7uF
C122 "Capacitor" 0402_065 2510,4420 r270 bottom value=0.1uF
C123 "Capacitor" 0603L 2560,4420 r270 bottom value=2.2uF
C124 "Capacitor" 0402 2350,4520 r90 bottom value=33pF
C125 "Capacitor" 0402 2239,4479 r0 bottom value=33pF
C200 "Capacitor" 0805 2085.96,3282.96 r180 bottom value=22uF
C201 "Capacitor" 0805 2102.4,3375 r0 bottom value=22uF
C202 "Capacitor" 0805 2102.4,3465 r0 bottom value=22uF
C203 "Capacitor" 0805 2232.4,3190 r180 bottom value=22uF
C204 "Capacitor" 0805 2232.4,3275 r180 bottom value=22uF
C205 "Capacitor" 0402 2232.4,3355 r0 bottom value=6800pF
C208 "Capacitor" 0402_065 2550,3555 r180 bottom value=0.1uF
C209 "Capacitor" 0603L 2374.45,3311.83 r90 bottom value=1000pF
C210 "CAPP_POS1NEG23" GX_3TERM 2790,3755 r180 bottom value=560uF
C211 "CAPP_POS1NEG23" GX_3TERM 2790,3755 r180 top value=560uF
C212 "Capacitor" 0805 2790,3338.52 r180 bottom value=100uF
C213 "Capacitor" 0805 2790,3258.52 r180 bottom value=100uF
C214 "Capacitor" 0805 2790,3178.52 r180 bottom value=100uF
C215 "Capacitor" 0805 2790,3598.52 r180 bottom value=100uF
C216 "Capacitor" 0805 2790,3518.52 r180 bottom value=100uF
C217 "Capacitor" 0805 2790,3428.52 r180 bottom value=100uF
C220 "Capacitor" 0603L 2185,3540 r0 top value=1uF
C221 "Capacitor" 0603 2185,3595 r180 top value=4.7uF
C222 "Capacitor" 0402_065 2510,3685 r270 bottom value=0.1uF
C223 "Capacitor" 0603L 2560,3685 r270 bottom value=2.2uF
C224 "Capacitor" 0402 2318.62,3776 r0 bottom value=33pF
C300 "Capacitor" 0805 2086,2549 r180 bottom value=22uF
C301 "Capacitor" 0805 2102.4,2735 r0 bottom value=22uF
C302 "Capacitor" 0805 2102.4,2645 r0 bottom value=22uF
C303 "Capacitor" 0805 2232.4,2460 r180 bottom value=22uF
C304 "Capacitor" 0805 2232.4,2545 r180 bottom value=22uF
C305 "Capacitor" 0402 2232.4,2625 r0 bottom value=6800pF
C308 "Capacitor" 0402_065 2550,2825 r180 bottom value=0.1uF
C309 "Capacitor" 0603L 2380,2572.4 r90 bottom value=1000pF
C310 "CAPP_POS1NEG23" GX_3TERM 2790,3020 r180 top value=560uF
C311 "CAPP_POS1NEG23" GX_3TERM 2790,3020 r180 bottom value=560uF
C312 "Capacitor" 0805 2790,2612.4 r180 bottom value=100uF
C313 "Capacitor" 0805 2790,2522.4 r180 bottom value=100uF
C314 "Capacitor" 0805 2790,2442.4 r180 bottom value=100uF
C315 "Capacitor" 0805 2790,2862.4 r180 bottom value=100uF
C316 "Capacitor" 0805 2790,2782.4 r180 bottom value=100uF
C317 "Capacitor" 0805 2790,2692.4 r180 bottom value=100uF
C320 "Capacitor" 0603L 2185,2810 r0 top value=1uF
C321 "Capacitor" 0603 2185,2865 r180 top value=4.7uF
C322 "Capacitor" 0402_065 2510,2955 r270 bottom value=0.1uF
C323 "Capacitor" 0603L 2560,2955 r270 bottom value=2.2uF
C324 "Capacitor" 0402 2308,3030 r0 bottom value=33pF
C400 "Capacitor" 0805 2084.51,1805 r180 bottom value=22uF
C401 "Capacitor" 0805 2102.4,1990 r0 bottom value=22uF
C402 "Capacitor" 0805 2102.4,1900 r0 bottom value=22uF
C403 "Capacitor" 0805 2232.4,1800 r180 bottom value=22uF
C404 "Capacitor" 0805 2232.4,1715 r180 bottom value=22uF
C405 "Capacitor" 0402 2232.4,1880 r0 bottom value=6800pF
C408 "Capacitor" 0402_065 2550,2080 r180 bottom value=0.1uF
C409 "Capacitor" 0603L 2374.45,1836.83 r90 bottom value=1000pF
C411 "CAPP_POS1NEG23" GX_3TERM 2790,2280 r180 bottom value=560uF
C412 "CAPP_POS1NEG23" GX_3TERM 2790,2280 r180 top value=560uF
C413 "Capacitor" 0805 2790,1870 r180 bottom value=100uF
C414 "Capacitor" 0805 2790,1780 r180 bottom value=100uF
C415 "Capacitor" 0805 2790,1700 r180 bottom value=100uF
C416 "Capacitor" 0805 2790,2120 r180 bottom value=100uF
C417 "Capacitor" 0805 2790,2040 r180 bottom value=100uF
C418 "Capacitor" 0805 2790,1950 r180 bottom value=100uF
C420 "Capacitor" 0603L 2185,2065 r0 top value=1uF
C421 "Capacitor" 0603 2185,2120 r180 top value=4.7uF
C422 "Capacitor" 0402_065 2510,2210 r270 bottom value=0.1uF
C423 "Capacitor" 0603L 2560,2210 r270 bottom value=2.2uF
C424 "Capacitor" 0402 2310,2317 r0 bottom value=33pF
C500 "Capacitor" 0402 3600,3965 r0 bottom value=0.1uF
C505 "Capacitor" 0402 3600,3420 r0 bottom value=0.1uF
FID1 "Fiducial" Fiducial10-20 210,6340 r0 top
FID2 "Fiducial" Fiducial10-20 640,300 r0 top
FID3 "Fiducial" Fiducial10-20 4320,300 r0 top
H1 "NY PMS 440 0025 PH" "NY PMS 440 0025 PH" 250,250 r0 top locked
H2 "NY PMS 440 0025 PH" "NY PMS 440 0025 PH" 250,6750 r0 top locked
H3 "NY PMS 440 0025 PH" "NY PMS 440 0025 PH" 4750,6750 r0 top locked
H4 "NY PMS 440 0025 PH" "NY PMS 440 0025 PH" 4750,250 r0 top locked
H5 "1902C" Keystone_1902C 250,250 r0 top locked
H6 "1902C" Keystone_1902C 250,6750 r0 top locked
H7 "1902C" Keystone_1902C 4750,6750 r0 top locked
H8 "1902C" Keystone_1902C 4750,250 r0 top locked
J1 "Header_4x2" CONN_PEC04DAAN 450,1912 r270 top
J2 "Header_5x2" CONN_5103308-1 540,5910 r0 top
J3 "Header_3x2" Sullins_PBC03DAAN 612,5156 r0 top
J9 "TSW-102-07-G-S" TSW-102-07-G-S 247,1592 r270 top
J500 "U.FL-R-SMT-1(01)" CONN_UFL-R-SMT-1 3605,3775 r270 bottom
J501 "U.FL-R-SMT-1(01)" CONN_UFL-R-SMT-1 3605,3600 r90 bottom
J502 "TSW-102-07-G-S" TSW-102-07-G-S 3271.02,3670 r0 bottom
JP1 "TSW-102-07-G-S" TSW-102-07-G-S 290,4672.14 r90 top
L100 "SLC1480-201MLB" SLC1480 2700,4120 r0 top value=200nH
L200 "Inductor_Iron" SLC1480 2700,3388.52 r0 top value=200nH
L300 "Inductor_Iron" SLC1480 2700,2652.4 r0 top value=200nH
L400 "Inductor_Iron" SLC1480 2700,1910 r0 top value=200nH
LBL1 "THT-14-423-10" Label_650x200 1288,213 r0 top
LED1 "150060GS75000" WL-SMCW_GREEN 298.72,5620 r0 top value=Green
Logo2 "FCC disclaimer" FCC_disclaimer 1684,6633 r0 top
NT100 "Net-Tie" Net-Tie_10mil 2324.84,4381.91 r270 bottom net-tie
NT200 "Net-Tie" Net-Tie_10mil 2324,3650 r270 bottom net-tie
NT300 "Net-Tie" Net-Tie_10mil 2324.84,2920 r270 bottom net-tie
NT400 "Net-Tie" Net-Tie_10mil 2324.84,2170 r270 bottom net-tie
Q500 "CSD16408Q5" DQH0008A 3201.02,4030 r180 bottom value=25V
R1 "ERJ-2RKF1003X" 0402 308,1437 r180 top value=100k
R2 "ERJ-2RKF1003X" 0402 560,1230 r270 top value=100k
R3 "CRCW040217K8FKED" 0402 560,1370 r270 top value=17.8k
R5 "RC0402FR-071KL" 0402 470,5620 r180 top value=1.00k
R6 "CRCW040224K9FKED" 0402 190,5170 r270 top value=24.9k
R7 "RC0402FR-0710KL" 0402 291.68,5172 r90 top value=10.0k
R10 "CRCW04020000Z0ED" 0402 4578,3148 r0 top value=0
R11 "CRCW04020000Z0ED" 0402 4576,2975 r180 top value=0
R12 "Resistor" 0402 3329,3284.48 r270 top value=49.9
R13 "Resistor" 0402 3370,2990 r0 top value=49.9
R100 "CRCW040210R0JNED" 0402 2157,4194.57 r90 top value=10
R101 "Resistor" 0402 2108,4435 r270 bottom value=10.0k
R102 "Resistor" 0402 2053,4433 r90 bottom value=10.0k
R103 "Resistor" 0402 2193,4495.38 r270 top value=10.0k
R104 "Resistor" 0402 2095,4430 r180 top value=10.0k
R105 "Resistor" 0402 2098,4537 r0 top value=10.0k
R106 "Resistor" 0402 2095,4480 r180 top value=10.0k
R107 "Resistor" 0402 2120,4516.46 r0 bottom value=10.0k
R108 "Resistor" 0402 2120,4576.46 r180 bottom value=10.0k
R109 "Resistor" 0402 2535.57,4491.46 r180 bottom value=10.0k
R111 "Resistor" 0402 2211,4547.45 r270 bottom value=49.9
R112 "Resistor" 0402 2266,4548 r270 bottom value=49.9
R113 "Resistor" 0402 2535.57,4341.46 r180 bottom value=0
R114 "Resistor" 0805 2460,4045.55 r270 bottom value=3.3
R115 "Resistor" 0805 2540,4045.55 r270 bottom value=3.3
R200 "CRCW040210R0JNED" 0402 2161,3458 r90 top value=10
R201 "Resistor" 0402 2167.5,3762 r270 bottom value=10.0k
R202 "Resistor" 0402 2119,3677 r180 bottom value=10.0k
R213 "Resistor" 0402 2535.57,3606.46 r180 bottom value=0
R214 "Resistor" 0805 2540,3310 r270 bottom value=3.3
R215 "Resistor" 0805 2460,3310 r270 bottom value=3.3
R219 "Resistor" 0402 2234.45,3768.52 r270 bottom value=49.9
R300 "CRCW040210R0JNED" 0402 2157.44,2726 r90 top value=10
R301 "Resistor" 0402 2170,3030 r270 bottom value=10.0k
R302 "Resistor" 0402 2119,2945 r180 bottom value=10.0k
R313 "Resistor" 0402 2535.57,2876.46 r180 bottom value=0
R314 "Resistor" 0805 2460,2580 r270 bottom value=3.3
R315 "Resistor" 0805 2540,2580 r270 bottom value=3.3
R319 "Resistor" 0402 2235,3032.4 r270 bottom value=49.9
R400 "CRCW040210R0JNED" 0402 2162,1984 r90 top value=10
R401 "Resistor" 0402 2175,2288 r270 bottom value=10.0k
R402 "Resistor" 0402 2120,2200 r180 bottom value=10.0k
R413 "Resistor" 0402 2535.57,2131.46 r180 bottom value=0
R414 "Resistor" 0805 2460,1835 r270 bottom value=3.3
R415 "Resistor" 0805 2540,1835 r270 bottom value=3.3
R419 "Resistor" 0402 2234.49,2293.52 r270 bottom value=49.9
R500 "Resistor" 2512 3505,4070 r180 bottom value=0.01
R501 "Resistor" 0402 3600,3905 r0 bottom value=49.9
R502 "Resistor" 0402 3231.02,3820 r90 bottom value=1.0
R503 "Resistor" 0402 3311.02,3820 r90 bottom value=10.0k
R505 "Resistor" 0402 3600,3475 r180 bottom value=49.9
T1 "CB35-36-CY" CB35-36-CY 690,3880 r0 top
T2 "CB35-36-CY" CB35-36-CY 680,2600 r0 top
T3 "CB35-36-CY" CB35-36-CY 4580,4100 r180 top
T4 "CB35-36-CY" CB35-36-CY 4580,3510 r180 top
T5 "CB35-36-CY" CB35-36-CY 4570,2700 r180 top
T6 "CB35-36-CY" CB35-36-CY 4570,2120 r180 top
TP1 "5000" Keystone5000 1756,3212 r0 top
TP2 "5016" Testpoint_Keystone_Compact 1755,2973 r0 top
TP3 "5000" Keystone5000 260,1000 r0 top
TP4 "5011" Keystone5011 500,6319 r0 top
TP5 "5012" Keystone5012 1070,6110 r0 top
TP6 "5012" Keystone5012 1087,5776 r0 top
TP7 "5012" Keystone5012 698,5619 r0 top
TP8 "5012" Keystone5012 784,6294 r0 top
TP9 "5016" Testpoint_Keystone_Compact 1260,5420 r0 top
TP10 "5010" Keystone5010 4846,3204 r0 top
TP11 "5011" Keystone5011 4848,3037 r0 top
TP12 "5012" Keystone5012 3404,3129 r90 top
TP13 "5010" Keystone5010 3181,3251.2 r90 top
TP14 "5010" Keystone5010 4266,3819 r90 top
TP15 "5011" Keystone5011 3200,3005 r180 top
TP16 "5016" Testpoint_Keystone_Compact 3630,3030 r0 bottom
TP17 "5001" Keystone5001 4277,2422 r90 top
U1 "TPS82130SILR" SIL0008D_SMD 400,1330 r0 top
U100 "TPS546D24ARVFR" RVF0040A_SMD_NV 2315,4270 r180 bottom
U200 "TPS546D24ARVFR" RVF0040A_SMD_NV 2315,3535 r180 bottom
U300 "TPS546D24ARVFR" RVF0040A_SMD_NV 2315,2805 r180 bottom
U400 "TPS546D24ARVFR" RVF0040A_SMD_NV 2315,2060 r180 bottom

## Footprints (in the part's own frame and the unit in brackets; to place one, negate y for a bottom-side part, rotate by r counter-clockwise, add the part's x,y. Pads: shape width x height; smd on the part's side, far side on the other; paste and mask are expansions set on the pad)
0402 [mm] "0402 from SM-752 data"
  rect 0.8x0.6 smd: 1(-0.6,0) 2(0.6,0)
  silkscreen extent -1.22,-0.52 1.22,0.52, body extent -0.55,-0.3 0.55,0.3, height 0.6
0402_065 [mm] "0402"
  rect 0.8x0.6 smd: 1(-0.6,0) 2(0.6,0)
  silkscreen extent -1.22,-0.52 1.22,0.52, body extent -0.55,-0.3 0.55,0.3, height 0.65
0603 [mm] "0603 from SM-752 data"
  rect 1x0.95 smd: 1(-0.8,0) 2(0.8,0)
  silkscreen extent -1.52,-0.69 1.52,0.69, body extent -0.87,-0.47 0.87,0.47, height 1
0603L [mm] "0603 from SM-752 data"
  rect 0.8x0.85 smd: 1(-0.7,0) 2(0.7,0)
  silkscreen extent -0.07,-0.33 0.07,0.33, body extent -0.87,-0.47 0.87,0.47, height 1
0805 [mm] "0805 from SM-752 data"
  rect 1.3x1.5 smd: 1(-0.85,0) 2(0.85,0)
  silkscreen extent -1.72,-0.97 1.72,0.97, body extent -1.1,-0.72 1.1,0.72, height 1.45
1210_270 [mm] "1210"
  rect 1.3x2.7 smd: 1(-1.45,0) 2(1.45,0)
  silkscreen extent -2.32,-1.57 2.32,1.57, body extent -1.7,-1.35 1.7,1.35, height 2.7
2512 [mm] "Chip Resistor, Body 6.3x3.2mm, IPC Medium Density"
  rect 1.3x3.4 smd: 1(-2.95,0) 2(2.95,0)
  silkscreen extent -1.9,-1.6 1.9,1.6, body extent -3.22,-1.67 3.22,1.67, height 0.71
CB35-36-CY [mil] "Terminal 50A Lug"
  rect 550x380 hole 188 copper offset -45,0 paste-190: 1(0,0)
  body extent -960,-189 230,191, height 614
CONN_5103308-1 [mm] "TE Connectivity (AMP) Rev E datasheet"
  rect 1.65x1.65 hole 1.016 mask+0: 1(-5.08,-1.27)
  round 1.65 hole 1.016 mask+0: 2(-5.08,1.27) 3(-2.54,-1.27) 4(-2.54,1.27) 5(0,-1.27) 6(0,1.27) 7(2.54,-1.27) 8(2.54,1.27) 9(5.08,-1.27) 10(5.08,1.27)
  silkscreen extent -10.16,-5.33 10.16,4.57, body extent -10.16,-4.57 10.16,4.57, height 9.87
CONN_PEC04DAAN [mm] "SULLINS"
  rect 1.65x1.65 hole 1.016 mask+0: 1(-3.81,-1.27)
  round 1.65 hole 1.016 mask+0: 2(-3.81,1.27) 3(-1.27,-1.27) 4(-1.27,1.27) 5(1.27,-1.27) 6(1.27,1.27) 7(3.81,-1.27) 8(3.81,1.27)
  silkscreen extent -6.18,-2.6 5.08,2.54, body extent -5.08,-2.54 5.08,2.54, height 8.38
CONN_UFL-R-SMT-1 [mm] "Hirose recommended land pattern http://www.hirose.co.jp/cataloge_hp/e32119372.pdf 2009.2"
  rect 1.05x1 smd paste-0.1 mask-0.1: 1(-1.525,0)
  rect 2.2x1.05 smd paste-2 mask-2: 2(0,1.475) 3(0,-1.475)
  rect 2x0.9 on Bottom Paste: 2(0,1.5) 3(0,-1.5)
  rect 2x0.9 on Bottom Solder: 2(0,1.5) 3(0,-1.5)
  Top Layer keep-out region: -0.8,0.7 1.1,0.7 1.1,-0.7 -0.8,-0.7
  silkscreen extent -1.7,-1.7 1.7,1.7, body extent -1.55,-1.5 1.55,1.5, height 1.27
DQH0008A [mm] "TI"
  rrect39% 0.91x0.51 smd paste-0.05 mask-0.05: 1(-2.795,1.905) 2(-2.795,0.635) 3(-2.795,-0.635) 4(-2.795,-1.905) 5(2.795,-1.905) 6(2.795,-0.635) 7(2.795,0.635) 8(2.795,1.905)
  rrect9% 1.14x1.23 on Bottom Paste: 9(-1.06,-1.43) 9(-1.06,0) 9(-1.06,1.43) 9(0.28,-1.43) 9(0.28,0) 9(0.28,1.43) 9(1.62,-1.43) 9(1.62,0) 9(1.62,1.43)
  rrect2% 4.02x4.42 on Bottom Solder: 9(0.38,0)
  rrect2% 4.93x4.52 smd paste-3 mask-3: 9(0.786,0)
  silkscreen extent -3.18,-2.68 3.18,2.68, body extent -3.05,-2.55 3.05,2.55, height 1.06
FCC_disclaimer [mil]
Fiducial10-20 [mm]
  round 1 smd mask+0.5: 1(0,0)
  Top Layer keep-out circle w1.178: c0,0 r0.5
GX_3TERM [mm] "PANASONIC"
  rect 2.8x2.4 smd: 1(-3.4,0) 3(3.4,0)
  rect 1.3x5.1 smd: 2(-0.85,0)
  Top Layer region: -0.7,-1.2 1.2,-1.2 1.2,1.2 -0.7,1.2
  silkscreen extent -4.45,-2.4 3.8,2.4, body extent -3.75,-2.25 3.75,2.25, height 2.01
Keystone5000 [mil] "For Keystone 500x miniature loop terminals"
  round 80 hole 40: 1(0,0)
  silkscreen extent -52,-52 52,52, body extent -49,-49 49,49, height 182
Keystone5001 [mil] "For Keystone 500x miniature loop terminals"
  round 80 hole 40: 1(0,0)
  silkscreen extent -52,-52 52,52, body extent -49,-49 49,49, height 182
Keystone5010 [mil] "Keystone Multipurpose loops"
  round 87 hole 63: 1(0,0)
  silkscreen extent -70,-70 70,70, body extent -63,-63 63,62, height 319
Keystone5011 [mil] "Keystone Multipurpose loops"
  round 87 hole 63: 1(0,0)
  silkscreen extent -70,-70 70,70, body extent -63,-63 63,62, height 319
Keystone5012 [mil] "Keystone Multipurpose loops"
  round 87 hole 63: 1(0,0)
  silkscreen extent -70,-70 70,70, body extent -63,-63 63,62, height 319
Keystone_1902C [mil] "Hex Standoff, 4-40 threaded, nylon"
  round 1 on Mech3: 0(0,0)
  body extent -145,-126 146,126, height 501
Label_650x200 [mil] "Thermal Transfer Label"
  round 1 on Mech13: 0(0,0)
  silkscreen extent -325,-100 325,100, body extent -325,-100 325,100, height 1
Net-Tie_10mil [mil] "10mil net tie, no solder mask opening, no solder paste"
  rect 10x10 smd paste-5 mask-5: 1(-10,0) 2(10,0)
  Top Layer region: -6,5 6,5 6,-5 -6,-5
"NY PMS 440 0025 PH" [mm] "4-40 nylon screw and mounting hole"
  round 8 hole 3.2: 1(0,0)
  body extent -3.3,-3.3 3.3,3.3, height 2.69
RVF0040A_SMD_NV [mm] "LQFN-CLIP"
  rrect57% 0.7x0.35 smd paste-0.05 mask-0.05: 1(-2.4,2.75) 2(-2.4,2.25) 3(-2.4,1.75) 4(-2.4,1.25) 5(-2.4,0.75) 6(-2.4,0.25) 7(-2.4,-0.25) 8(-2.4,-0.75) 9(-2.4,-1.25) 10(-2.4,-1.75) 11(-2.4,-2.25) 12(-2.4,-2.75) 21(2.4,-2.75) 22(2.4,-2.25) 23(2.4,-1.75) 24(2.4,-1.25) 25(2.4,-0.75) 26(2.4,-0.25) 27(2.4,0.25) 28(2.4,0.75) 29(2.4,1.25) 30(2.4,1.75) 31(2.4,2.25) 32(2.4,2.75)
  rrect57% 0.35x0.7 smd paste-0.05 mask-0.05: 13(-1.75,-3.4) 14(-1.25,-3.4) 15(-0.75,-3.4) 16(-0.25,-3.4) 17(0.25,-3.4) 18(0.75,-3.4) 19(1.25,-3.4) 20(1.75,-3.4) 33(1.75,3.4) 34(1.25,3.4) 35(0.75,3.4) 36(0.25,3.4) 37(-0.25,3.4) 38(-0.75,3.4) 39(-1.25,3.4) 40(-1.75,3.4)
  rrect9% 1.43x1.08 on Bottom Paste: 41(-0.815,-1.92) 41(-0.815,-0.64) 41(-0.815,0.64) 41(-0.815,1.92) 41(0.815,-1.92) 41(0.815,-0.64) 41(0.815,0.64) 41(0.815,1.92)
  rrect6% 3.4x5.4 smd paste-2 mask-0.05: 41(0,0)
  silkscreen extent -2.7,-3.7 2.7,3.7, body extent -2.5,-3.5 2.5,3.5, height 1.52
SIL0008D_SMD [mm] "SIP, 8-Leads, Body 2.8x3.0mm, Pitch 0.65mm, Thermal Pad 1.9x1.1mm"
  rrect12% 1.04x0.85 on Top Paste: 0(0,-0.525) 0(0,0.525)
  rrect40% 0.6x0.5 smd paste-0.05 mask-0.05: 1(-1.05,0.975) 2(-1.05,0.325) 3(-1.05,-0.325) 4(-1.05,-0.975) 5(1.05,-0.975) 6(1.05,-0.325) 7(1.05,0.325) 8(1.05,0.975)
  rrect17% 1.2x2 smd paste-0.6 mask-0.05: 9(0,0)
  silkscreen extent -1.53,-1.63 1.53,1.63, body extent -1.4,-1.5 1.4,1.5, height 1.53
SLC1480 [mm] "Coilcraft"
  rect 4.95x6.35 smd: 1(-4.89,0) 2(4.89,0)
  silkscreen extent -6.73,-6.48 6.73,6.48, body extent -6.73,-6.48 6.73,6.48, height 8
SM_RADIAL_G [mm] "10 x 10.2mm:  Panasonic G"
  rect 4.1x2 smd: 1(-4.35,0) 2(4.35,0)
  silkscreen extent -5.35,-5.35 5.35,5.35, body extent -5.25,-5.25 5.25,5.25, height 10.5
Sullins_PBC03DAAN [mm] "Sullins 100mil, 2x3, 230 mil above insulator"
  rect 1.65x1.65 hole 1.016: 1(-1.27,2.54)
  round 1.65 hole 1.016: 2(1.27,2.54) 3(-1.27,0) 4(1.27,0) 5(-1.27,-2.54) 6(1.27,-2.54)
  silkscreen extent -2.67,-3.81 2.54,4.58, body extent -2.54,-3.81 2.54,3.81, height 8.38
Testpoint_Keystone_Compact [mil] "Compact SMT test point"
  rect 185x135 smd: 1(0,0)
  silkscreen extent -110,-80 110,80, body extent -75,-56 75,56, height 91
TSW-102-07-G-S [mm] "Samtec 100mil, 1x2, 230 mil above insulator"
  rrect50% 1.65x1.65 hole 1.016: 1(-1.27,0)
  round 1.65 hole 1.016: 2(1.27,0)
  silkscreen extent -3.17,-1.27 2.54,1.27, body extent -2.54,-1.27 2.54,1.27, height 8.38
WL-SMCW_GREEN [mm] "WURTH"
  rect 0.8x0.8 smd: 1(-0.8,0) 2(0.8,0)
  silkscreen extent -1.9,-0.8 1.2,0.8, body extent -0.85,-0.45 0.85,0.45, height 0.8

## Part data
C1 C2: library part CMP-0010663-1, "CAP, AL, 100 uF, 35 V, +/- 20%, 0.15 ohm, SMD", Cap_Case=G, Manufacturer=Panasonic, PartNumber=EEE-FC1V101P, Supplier Part Number 1=PCE4023CT-ND, Tolerance_%=20%, Value1="0.15 ohm", Value2=35V, ValueDisplayed=100uF
C3 C5 C100 C101 C102 C103 C104 C200 C201 C202 C203 C204 C300 C301 C302 C303 C304 C400 C401 C402 C403 C404: library part CMP-0007852-1, "CAP, CERM, 22 uF, 16 V, +/- 20%, X6S, 0805", Cap_Case=0805, Manufacturer=TDK, PartNumber=C2012X6S1C226M125AC, Supplier Part Number 1=445-14486-1-ND, TempCo=X6S, Tolerance_%=20%, Value1="0.00205 ohm", Value2=16V, ValueDisplayed=22uF
C4: library part CMP-0006236-2, "CAP, CERM, 0.01 uF, 50 V, +/- 5%, X7R, 0402", Cap_Case=0402, Manufacturer=Kemet, Supplier Part Number 1=399-7758-1-ND, TempCo=X7R, Tolerance_%=5%, Value1=Unknown, Value2=50V, ValueDisplayed=0.01uF
C7 C108 C122 C208 C222 C308 C322 C408 C422: library part CMP-0006204-2, "CAP, CERM, 0.1 uF, 16 V, +/- 10%, X5R, 0402", Cap_Case=0402, Manufacturer="Johanson Technology", PartNumber=160R07X104KV4T, Supplier Part Number 1=709-1129-1-ND, TempCo=X5R, Tolerance_%=10%, Value1=Unknown, Value2=16V, ValueDisplayed=0.1uF
C10 C11: library part CMP-0009220-2, "CAP, CERM, 47 uF, 10 V, +/- 10%, X7R, 1210", Cap_Case=1210, Manufacturer=MuRata, PartNumber=GRM32ER71A476KE15L, Supplier Part Number 1=490-5312-1-ND, TempCo=X7R, Tolerance_%=10%, Value1=Unknown, Value2=10V, ValueDisplayed=47uF
C105 C205 C305 C405: library part CMP-0006696-2, "CAP, CERM, 6800 pF, 50 V, +/- 10%, X7R, 0402", Cap_Case=0402, Manufacturer=MuRata, PartNumber=GRM155R71H682KA88D, Supplier Part Number 1=490-4515-1-ND, TempCo=X7R, Tolerance_%=10%, Value1=Unknown, Value2=50V, ValueDisplayed=6800pF
C109 C209 C309 C409: library part CMP-0006723-4, "CAP, CERM, 1000 pF, 100 V, +/- 5%, X7R, 0603", Cap_Case=0603, Manufacturer=AVX, PartNumber=06031C102JAT2A, Supplier Part Number 1=478-3698-1-ND, TempCo=X7R, Tolerance_%=5%, Value1="0.276 ohm", Value2=100V, ValueDisplayed=1000pF
C110 C111 C210 C211 C310 C311 C411 C412: library part CMP-0012239-3, "CAP, Aluminum Polymer, 560 uF, 2 V, +/- 20%, 0.003 ohm, SMD_7.3x1.9x4.3mm SMD", Cap_Case=D, Manufacturer=Panasonic, PartNumber=EEF-GX0D561L, Supplier Part Number 1=PCE5056CT-ND, Tolerance_%=20%, Value1="0.003 ohm", Value2=2V, ValueDisplayed=560uF
C112 C113 C114 C115 C116 C117 C212 C213 C214 C215 C216 C217 C312 C313 C314 C315 C316 C317 C413 C414 C415 C416 C417 C418: library part CMP-0008277-2, "CAP, CERM, 100 uF, 4 V, +/- 20%, X5R, 0805", Cap_Case=0805, Manufacturer=MuRata, PartNumber=GRM21BR60G107ME15L, Supplier Part Number 1=490-10510-1-ND, TempCo=X5R, Tolerance_%=20%, Value1=Unknown, Value2=4V, ValueDisplayed=100uF
C120 C220 C320 C420: library part CMP-0007405-4, "CAP, CERM, 1 uF, 25 V, +/- 10%, X7R, 0603", Cap_Case=0603, Manufacturer=MuRata, PartNumber=GRM188R71E105KA12D, Supplier Part Number 1=490-5307-1-ND, TempCo=X7R, Tolerance_%=10%, Value1=Unknown, Value2=25V, ValueDisplayed=1uF
C121 C221 C321 C421: library part CMP-0007058-4, "CAP, CERM, 4.7 uF, 10 V, +/- 10%, X7S, 0603", Cap_Case=0603, Manufacturer=TDK, PartNumber=C1608X7S1A475K080AC, Supplier Part Number 1=445-14258-1-ND, TempCo=X7S, Tolerance_%=10%, Value1=Unknown, Value2=10V, ValueDisplayed=4.7uF
C123 C223 C323 C423: library part CMP-0007499-4, "CAP, CERM, 2.2 uF, 16 V, +/- 10%, X7R, 0603", Cap_Case=0603, Manufacturer=MuRata, PartNumber=GRM188Z71C225KE43, Supplier Part Number 1=81-GRM188Z71C225KE3D, TempCo=X7R, Tolerance_%=10%, Value1=Unknown, Value2=16V, ValueDisplayed=2.2uF
C124 C125 C224 C324 C424: library part CMP-0006377-2, "CAP, CERM, 33 pF, 25 V, +/- 5%, C0G/NP0, 0402", Cap_Case=0402, Manufacturer=MuRata, PartNumber=GRM1555C1E330JA01D, Supplier Part Number 1=81-GRM1555C1E330JA1D, TempCo=C0G/NP0, Tolerance_%=5%, Value1=Unknown, Value2=25V, ValueDisplayed=33pF
C500 C505: library part CMP-0006607-2, "CAP, CERM, 0.1 uF, 25 V, +/- 10%, X5R, 0402", Cap_Case=0402, Manufacturer=MuRata, PartNumber=GRM155R61E104KA87D, Supplier Part Number 1=490-5920-1-ND, TempCo=X5R, Tolerance_%=10%, Value1=Unknown, Value2=25V, ValueDisplayed=0.1uF
FID1 FID2 FID3: library part CMP-0077181-1, "Fiducial mark.  There is nothing to buy or mount.", Manufacturer=N/A
H1 H2 H3 H4: library part CMP-0003617-1, "Machine Screw, Round, #4-40 x 1/4, Nylon, Philips panhead", Manufacturer="B&F Fastener Supply", Supplier Part Number 1=H542-ND
H5 H6 H7 H8: library part CMP-0003610-1, "Standoff, Hex, 0.5\"L #4-40 Nylon", Manufacturer=Keystone, Supplier Part Number 1=36-1902C-ND
J1: library part CMP-0054542-2, "Header, 100mil, 4x2, Tin, TH", Color=Black, Current_A=3A, Manufacturer="Sullins Connector Solutions", PartNumber=PEC04DAAN, Supplier Part Number 1=S2012E-04-ND, Voltage_V=1.8kV
J2: library part CMP-0054834-2, "Header (shrouded), 100mil, 5x2, Gold, TH", Manufacturer="TE Connectivity", PartNumber=5103308-1, Supplier Part Number 1=A33159-ND
J3: library part CMP-0054565-2, "Header, 100mil, 3x2, Gold, TH", Color=Black, Current_A=3A, Manufacturer="Sullins Connector Solutions", PartNumber=PBC03DAAN, Supplier Part Number 1=S2011E-03-ND, Voltage_V=1.8kV
J9 J502 JP1: library part CMP-0075405-3, "Header, 100mil, 2x1, Gold, TH", Color=Black, Current_A=6.3A, Manufacturer=Samtec, Supplier Part Number 1=SAM1029-02-ND, Voltage_V=550V
J500 J501: library part CMP-0075320-1, "Receptacle, Ultra Miniature Coaxial, Male Pin, 50 ohm, SMT", Color=Beige, Manufacturer="Hirose Electric Co. Ltd.", Supplier Part Number 1=H122041-ND
L100: library part CMP-0060886-1, "Inductor, Shielded, Ferrite, 200 nH, 55 A, 0.00015 ohm, SMD", Manufacturer=Coilcraft, Value1="0.00015 ohm", Value2=55A, ValueDisplayed=200nH
L200 L300 L400: library part CMP-0060886-1, "Inductor, Shielded, Ferrite, 200 nH, 55 A, 0.00015 ohm, SMD", Manufacturer=Coilcraft, PartNumber=SLC1480-201MLB, Value1="0.00015 ohm", Value2=55A, ValueDisplayed=200nH
LBL1: library part CMP-0003625-1, "Thermal Transfer Printable Labels, 0.650\" W x 0.200\" H - 10,000 per roll", Manufacturer=Brady, Supplier Part Number 1=97C5133
LED1: library part CMP-0002905-2, "LED, Green, SMD", Color=Green, Manufacturer="Wurth Elektronik", Value1=W, Value2=3.2V
Logo2: library part CMP-0074847-1, "FCC_disclaimer"
NT100 NT200 NT300 NT400: library part CMP-0078142-3, "Single point connection between nets.", Manufacturer=N/A
Q500: library part CMP-0000264-1, "MOSFET, N-CH, 25 V, 113 A, DQH0008A (VSON-CLIP-8)", Alternate Manufacturer=None, Manufacturer="Texas Instruments", Supplier Part Number 1=296-25321-1-ND, Value1=0.005, Value2="6.7 nC"
R1 R2: library part CMP-0026659-1, "RES, 100 k, 1%, 0.1 W, 0402", Manufacturer=Panasonic, Power_W=100mW, TempCo="100 ppm/C", Tolerance_%=1%, Value2=0.1W, Value_Code=100k
R3: library part CMP-0026051-3, "RES, 17.8 k, 1%, 0.063 W, AEC-Q200 Grade 0, 0402", Manufacturer=Vishay-Dale, Power_W=63mW, Supplier Part Number 1=541-17.8KLCT-ND, TempCo="100 ppm/C", Tolerance_%=1%, Value2=0.063W, Value_Code=17k8, ValueDisplayed=17.8k
R5: library part CMP-0026725-1, "RES, 1.00 k, 1%, 0.0625 W, 0402", Manufacturer="Yageo America", Power_W=62.5mW, Supplier Part Number 1=311-1.00KLRCT-ND, TempCo="100 ppm/C", Tolerance_%=1%, Value2=0.0625W, Value_Code=1k00, ValueDisplayed=1.00k
R6: library part CMP-0026196-2, "RES, 24.9 k, 1%, 0.063 W, AEC-Q200 Grade 0, 0402", Manufacturer=Vishay-Dale, Power_W=63mW, Supplier Part Number 1=541-24.9KLCT-ND, TempCo="100 ppm/C", Tolerance_%=1%, Value2=0.063W, Value_Code=24k9, ValueDisplayed=24.9k
R7: library part CMP-0078669-1, "RES, 10.0 k, 1%, 0.063 W, 0402", Manufacturer="Yageo America", Power_W=63mW, Supplier Part Number 1=311-10.0KLRCT-ND, TempCo="100 ppm/C", Tolerance_%=1%, Value2=0.063W, Value_Code=10k0, ValueDisplayed=10.0k
R10 R11: library part CMP-0026822-3, "RES, 0, 5%, 0.063 W, AEC-Q200 Grade 0, 0402", Manufacturer=Vishay-Dale, Power_W=63mW, Supplier Part Number 1=541-0.0JCT-ND, TempCo="200 ppm/C", Tolerance_%=5%, Value2=0.063W, Value_Code=0000, ValueDisplayed=0
R12 R13 R111 R112 R219 R319 R419 R501 R505: library part CMP-0026404-2, "RES, 49.9, 1%, 0.063 W, AEC-Q200 Grade 0, 0402", Manufacturer=Vishay-Dale, PartNumber=CRCW040249R9FKED, Power_W=63mW, Supplier Part Number 1=541-49.9LCT-ND, TempCo="100 ppm/C", Tolerance_%=1%, Value2=0.063W, Value_Code=49R9, ValueDisplayed=49.9
R100 R200 R300 R400: library part CMP-0026827-3, "RES, 10, 5%, 0.063 W, AEC-Q200 Grade 0, 0402", Manufacturer=Vishay-Dale, Power_W=63mW, Supplier Part Number 1=541-10JCT-ND, TempCo="200 ppm/C", Tolerance_%=5%, Value2=0.063W, Value_Code=10R0, ValueDisplayed=10
R101 R103 R107 R201 R301 R401: library part CMP-0025958-3, "RES, 10.0 k, 1%, 0.063 W, AEC-Q200 Grade 0, 0402", Manufacturer=Vishay-Dale, PartNumber=CRCW040210K0FKED, Power_W=63mW, Supplier Part Number 1=541-10.0KLCT-ND, TempCo="100 ppm/C", Tolerance_%=1%, Value2=0.063W, Value_Code=10k0, ValueDisplayed=DNP
R102: library part CMP-0025958-3, "RES, 10.0 k, 1%, 0.063 W, AEC-Q200 Grade 0, 0402", Manufacturer=Vishay-Dale, PartNumber=CRCW040210K0FKED, Power_W=63mW, Supplier Part Number 1=541-10.0KLCT-ND, TempCo="100 ppm/C", Tolerance_%=1%, Value2=0.063W, Value_Code=10k0, ValueDisplayed=8.25k
R104 R302: library part CMP-0025958-3, "RES, 10.0 k, 1%, 0.063 W, AEC-Q200 Grade 0, 0402", Manufacturer=Vishay-Dale, PartNumber=CRCW040210K0FKED, Power_W=63mW, Supplier Part Number 1=541-10.0KLCT-ND, TempCo="100 ppm/C", Tolerance_%=1%, Value2=0.063W, Value_Code=10k0, ValueDisplayed=68.1k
